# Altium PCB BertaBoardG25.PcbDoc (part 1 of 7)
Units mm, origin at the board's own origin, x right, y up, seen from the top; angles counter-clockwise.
Board outline 160 x 160 mm, 4 copper layers (Top, GND Plane, Power Plane, Bottom), stack 1.344 mm thick; 17 components, 112 nets, 2311 pads, 138 vias.
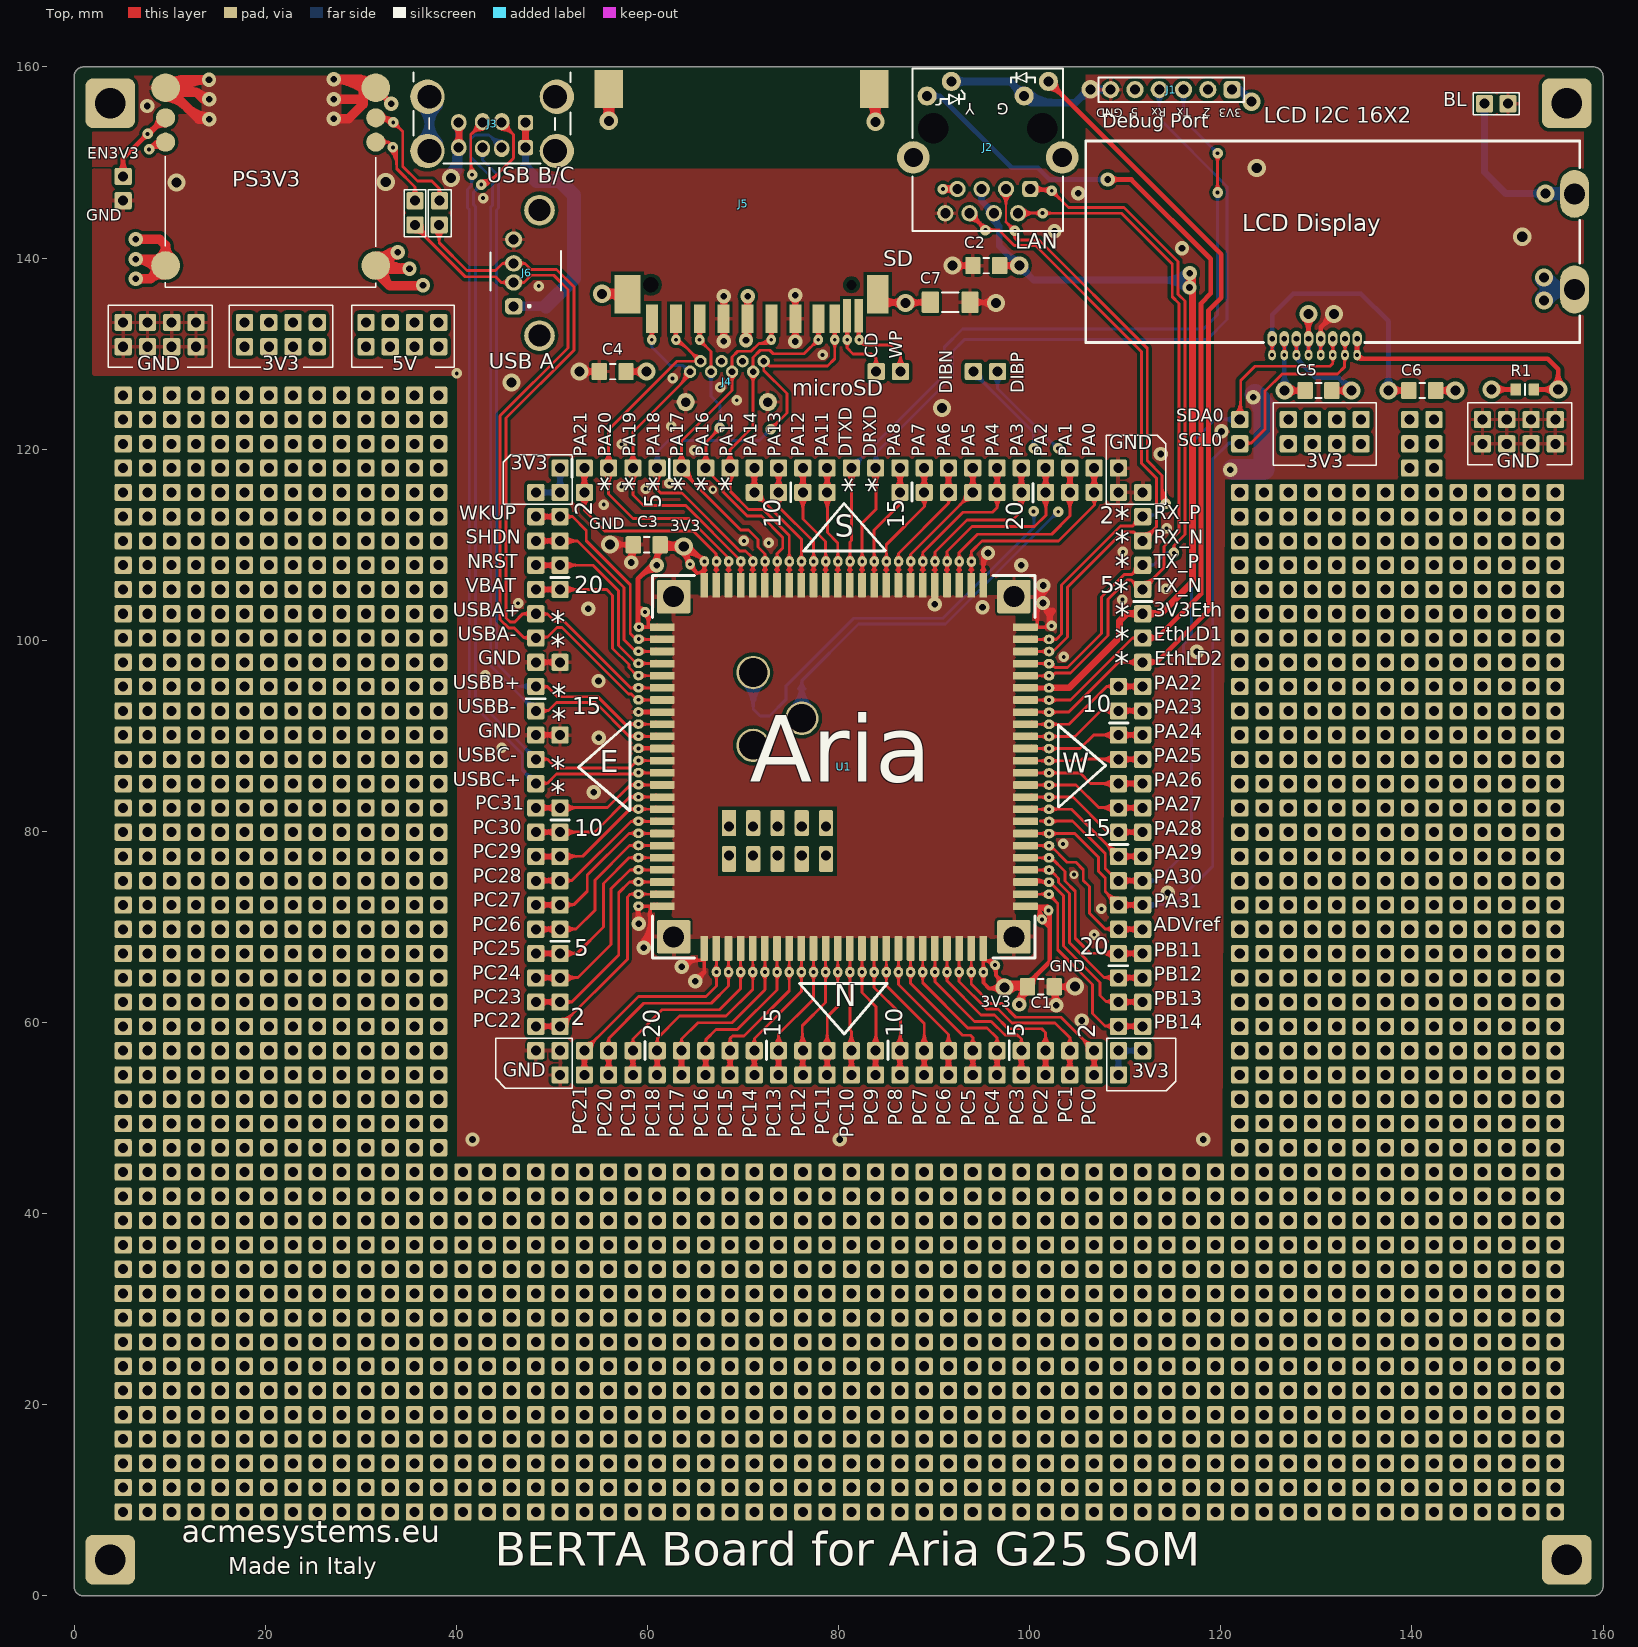
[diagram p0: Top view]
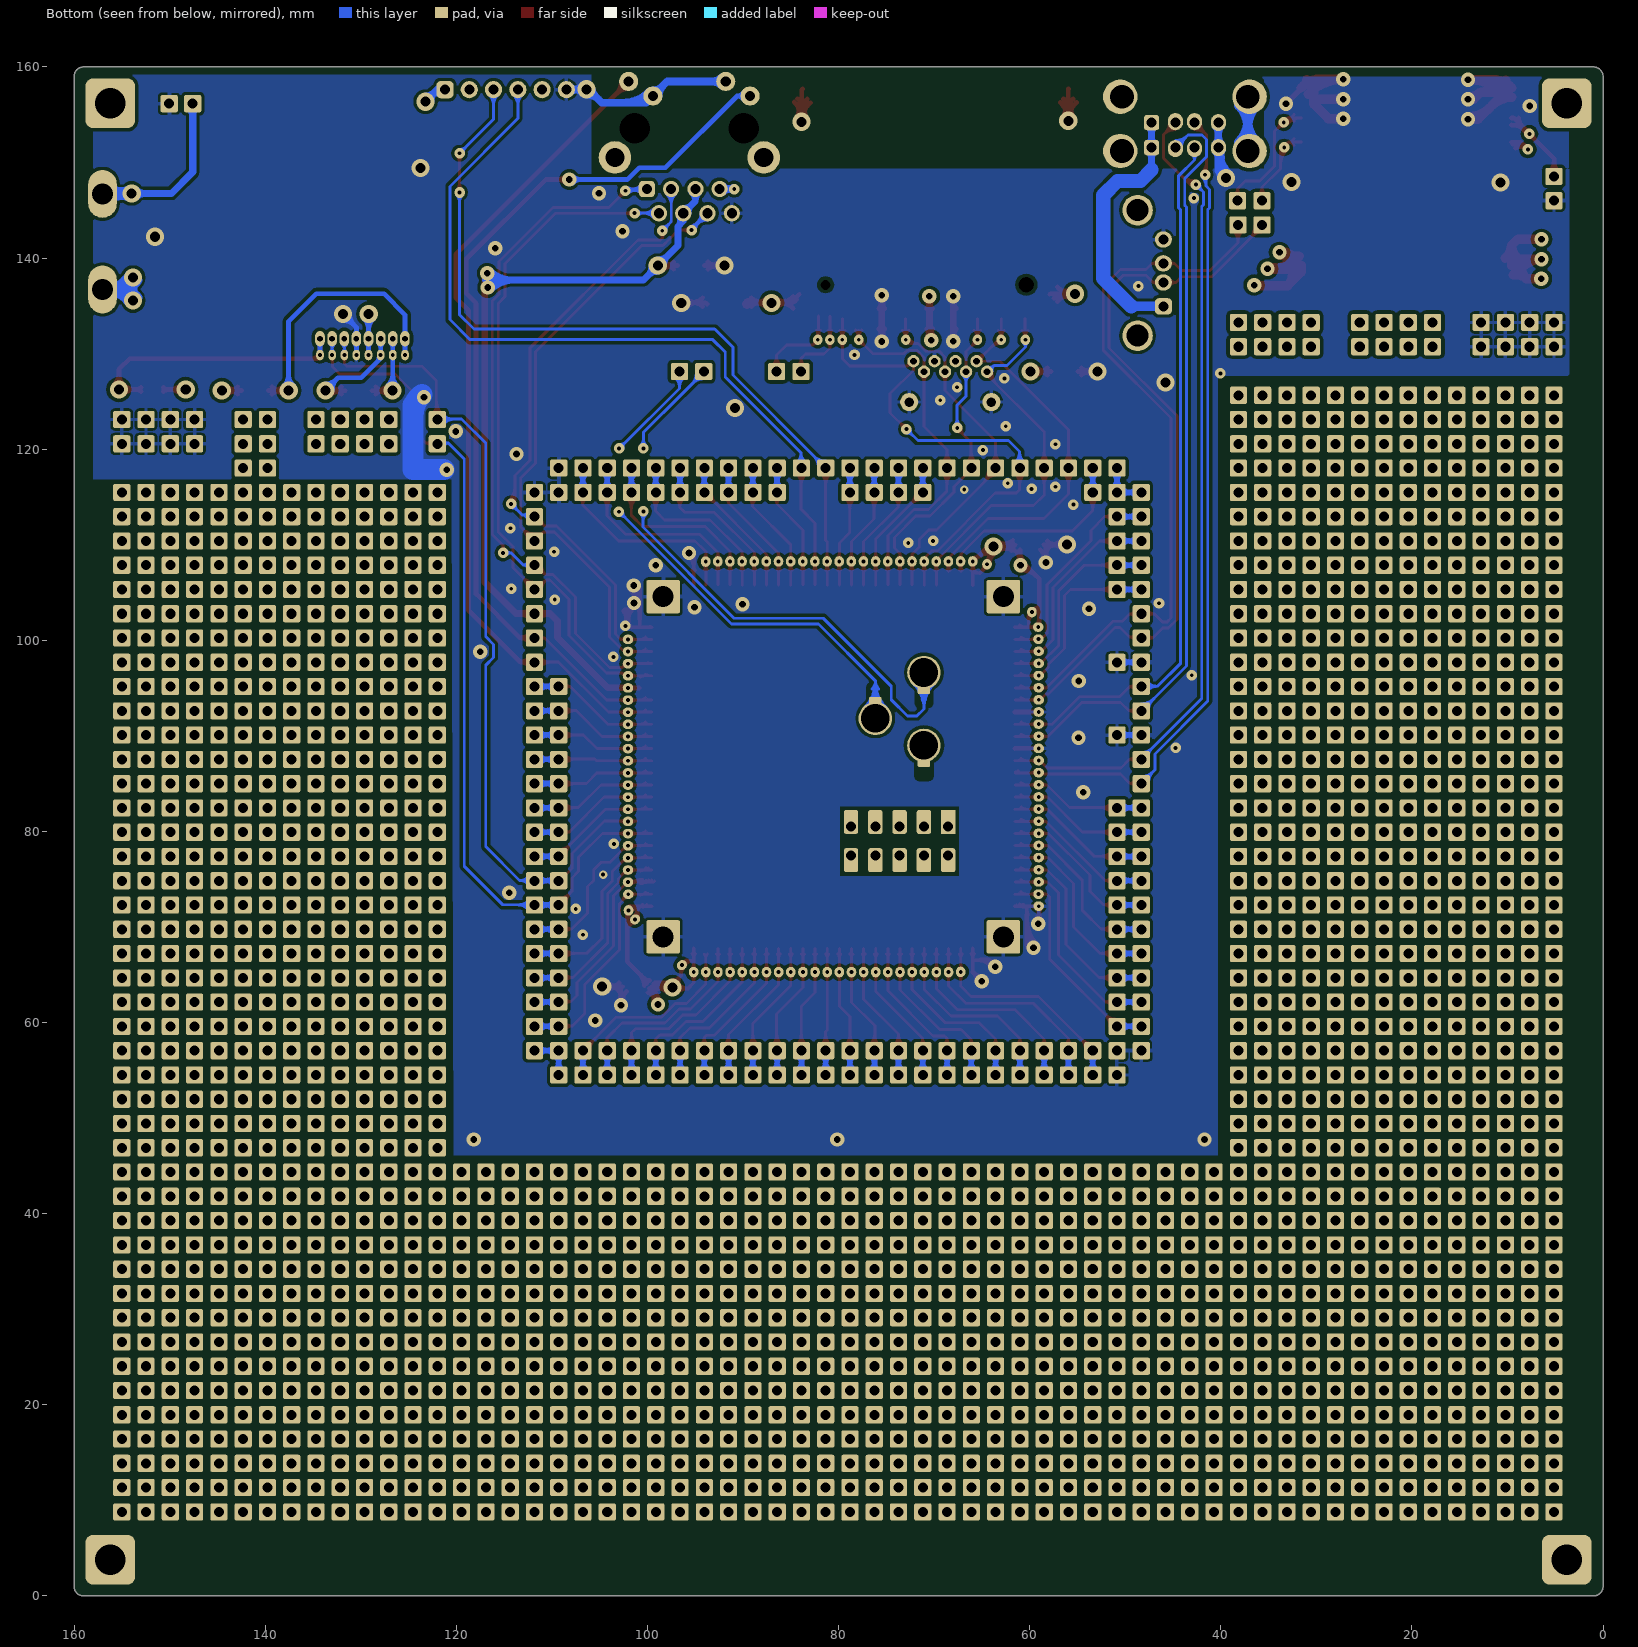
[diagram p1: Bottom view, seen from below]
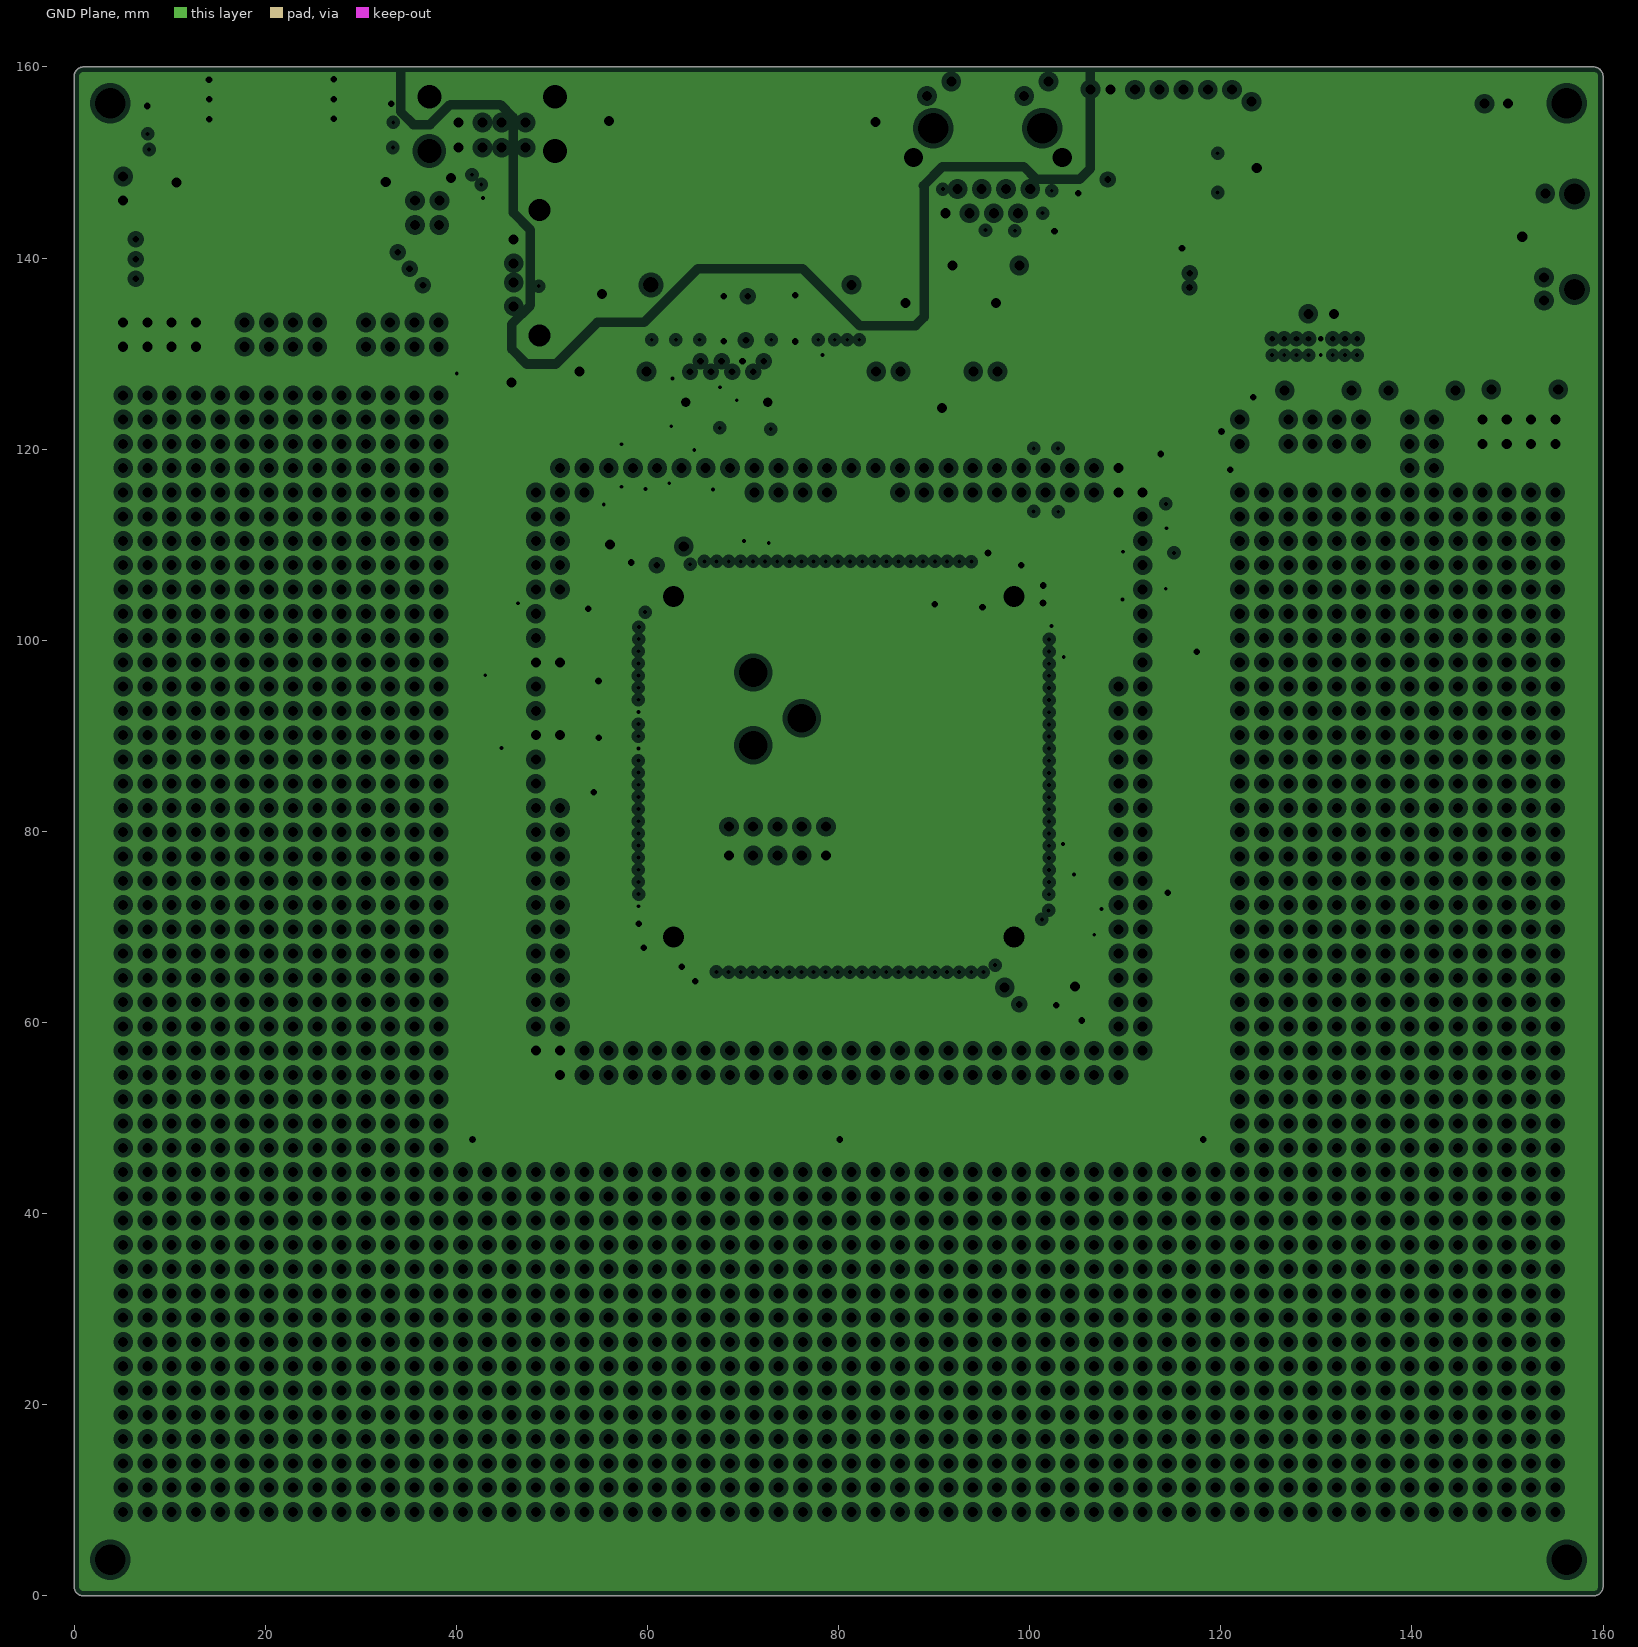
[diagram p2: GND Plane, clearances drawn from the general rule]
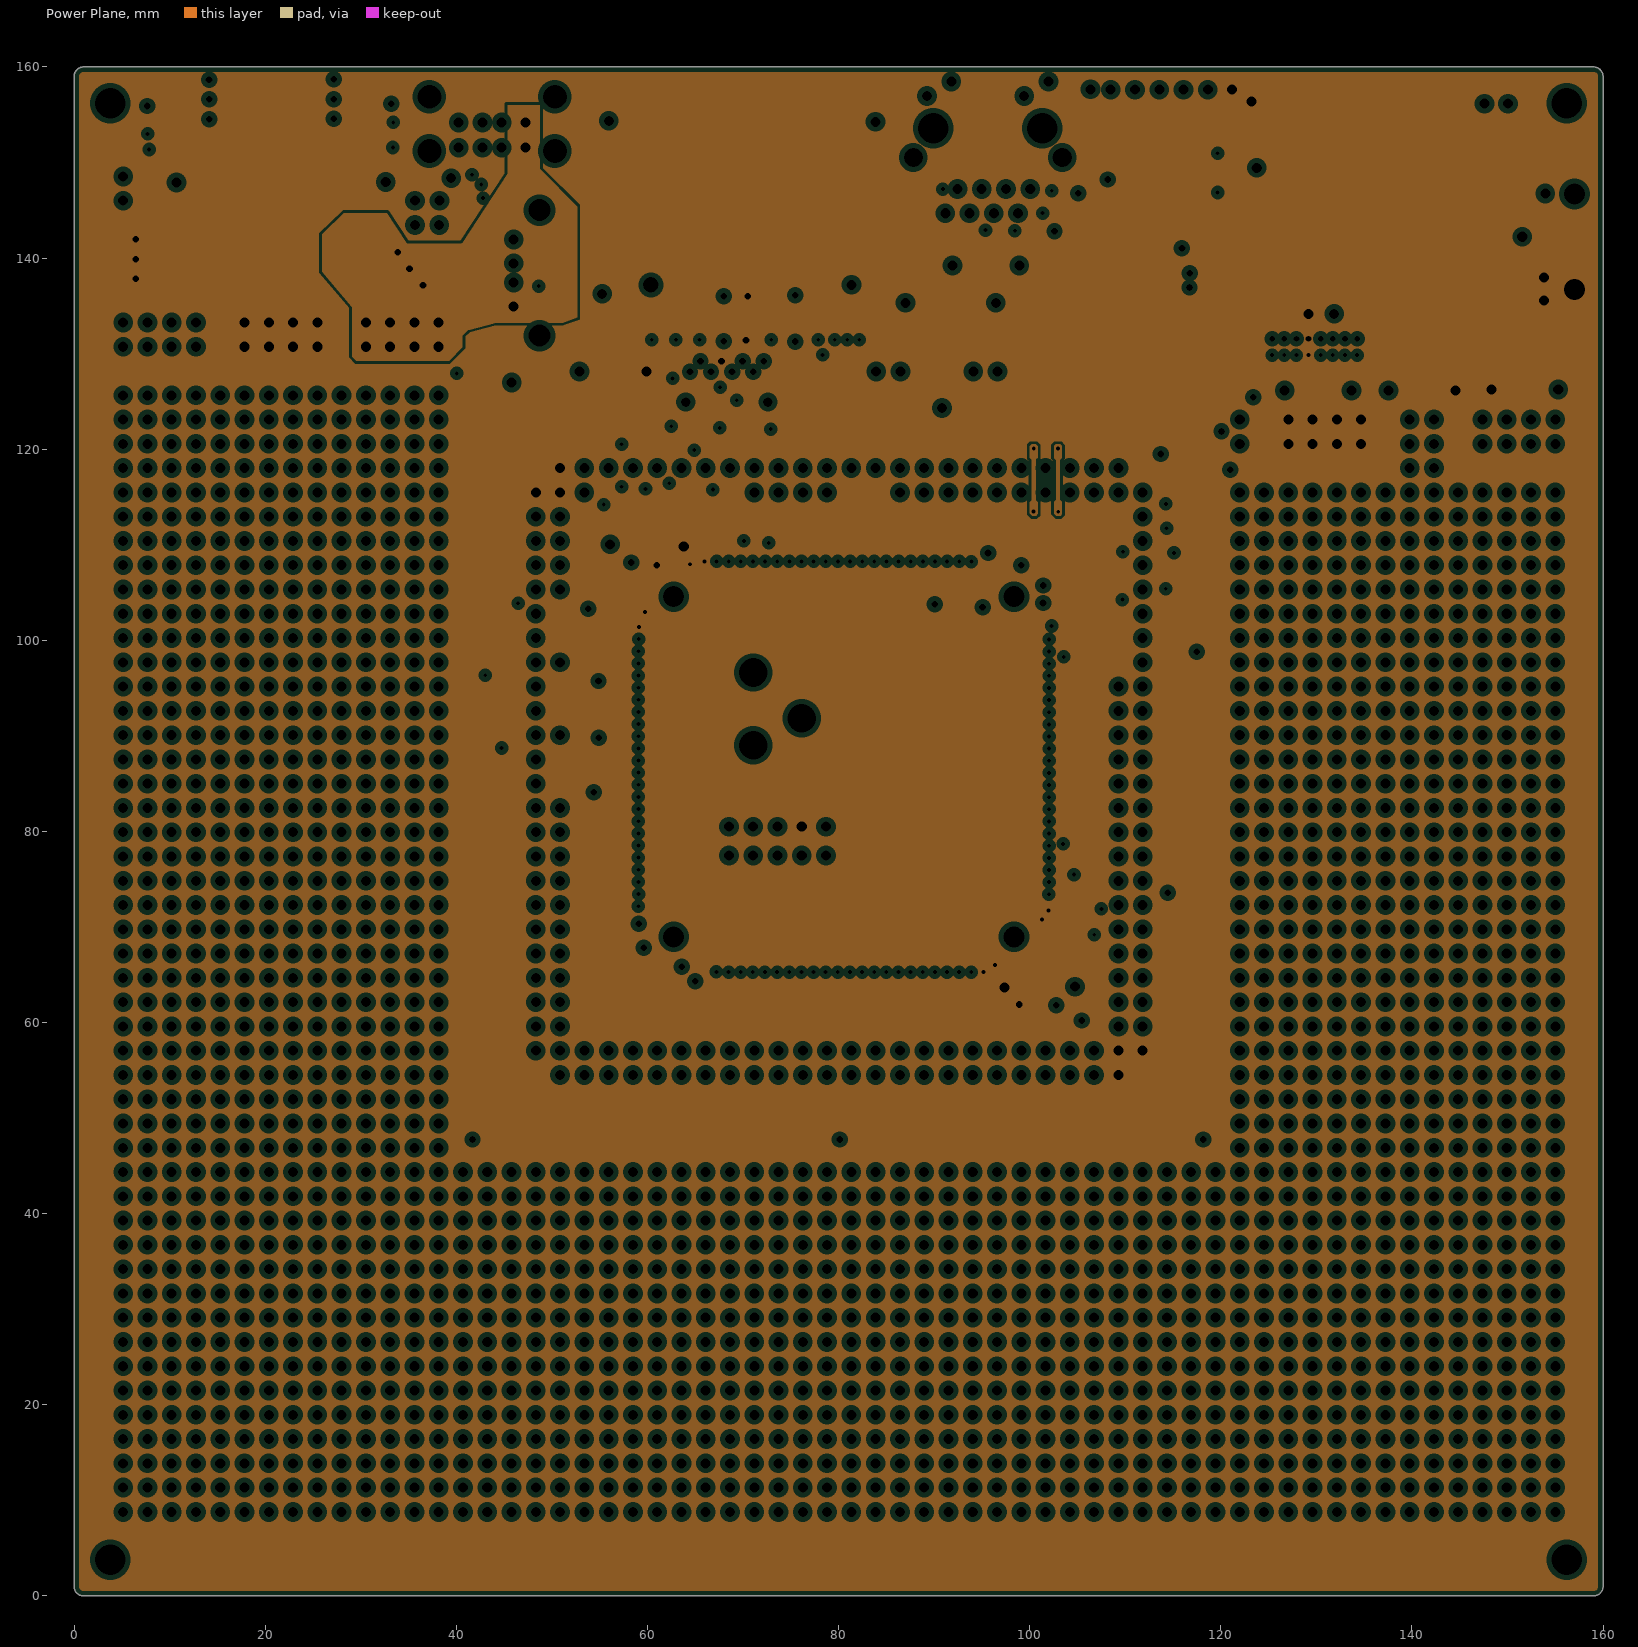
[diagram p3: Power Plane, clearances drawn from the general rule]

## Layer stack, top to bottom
Top: signal copper 0.017
Dielectric: core 0.6, pre preg 1080, Dk 4.8
GND Plane: plane copper 0.035, net (Multiple Nets)
Dielectric: prepreg 0.32, FR-4, Dk 4.8
Power Plane: plane copper 0.035, net (Multiple Nets)
Dielectric: core 0.32, FR-4, Dk 4.8
Bottom: signal copper 0.017

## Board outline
1,0 cw(c1.012,1.011) 0,1.023 0,159 0.001,159 cw(c1.012,158.988) 1.024,160 1,160 159,160 cw(c158.988,158.989) 160,158.977 160,1 cw(c158.989,1.012) 158.977,0

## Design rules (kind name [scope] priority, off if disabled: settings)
Clearance Clearance_Polygon [(IsPad or IsTrack or isVia) vs IsRegion] p1: gap=0.35
Clearance [All] p2: gap=0.29
ComponentClearance [All] p1: gap=0.254 collisioncheckmode=3 verticalgap=0.02 showdistances=FALSE
DiffPairsRouting [All] p1: maxlimit=0.254 minlimit=0.254 mostfreqgap=0.254 maxuncoupledlength=12.7
FabricationTestPointUsage TestPointUsage [All] p1: valid=0 allowmultiple=FALSE
FabricationTestpoint Testpoint [All] p1: side=3 testpointundercomponent=TRUE minsize=1.016 maxsize=2.54 preferedsize=1.524 minholesize=0 maxholesize=1.016 preferedholesize=0.813 testpointgrid=0.025 allowsidetop=TRUE allowsidebottom=TRUE usegrid=TRUE gridtolerance=0
HoleSize [All] p1: absolutevalues=TRUE maxlimit=4 minlimit=0.025 maxpercent=80.000 minpercent=20.000
HoleToHoleClearance [All] p1: gap=0.6 allowstackedmicrovias=TRUE
MinimumSolderMaskSliver [All] p1: minsoldermaskwidth=0.14
PasteMaskExpansion [All] p1: expansion=-0.025
PlaneClearance [All] p1: clearance=0.508
PlaneConnect [InNet('DIBN') or InNet('DIBP')] p1: planeconnectstyle=Direct reliefexpansion=0.508 reliefentries=4 reliefconductorwidth=0.3 reliefairgap=0.3
PlaneConnect PlaneConnect_1 [All] p2: planeconnectstyle=Relief reliefexpansion=0.508 reliefentries=4 reliefconductorwidth=0.35 reliefairgap=0.3
PolygonConnect Pads [(InPadClass('All Pads'))] p1: connectstyle=Relief reliefconductorwidth=0.4 reliefentries=4 polygonreliefangle="90 Angle" airgapwidth=0.254
PolygonConnect "Not Pads" [(NOT(InPadClass('All Pads')))] p2: connectstyle=Direct reliefconductorwidth=0.254 reliefentries=4 polygonreliefangle="90 Angle" airgapwidth=0.254
RoomDefinition BertaBoardG25 [InComponentClass('BertaBoardG25')] p1: confinementstyle=ConfineIn formatcopy=TRUE lockcomponents=FALSE outline -18.32,-12.99 353.11,-12.99 353.11,189.7 -18.32,189.7
RoutingVias [All] p1: holewidth=0.7 width=1.3 viastyle="Through Hole" minholewidth=0.4 minwidth=0.9 maxholewidth=1.1 maxwidth=1.9
ShortCircuit [All] p1: allowed=TRUE
SilkToSilkClearance [All] p1: silktosilkclearance=0.17
SilkToSolderMaskClearance SilkscreenOverComponentPads [IsPad] p1: minsilkscreentomaskgap=0.154 clearancetoexposedcopper=TRUE
SolderMaskExpansion [All] p1: expansion=0.075
Width [All] p1: maxlimit=3 minlimit=0.25 preferedwidth=0.5
15 further rules are at their usual default settings.

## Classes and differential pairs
differential pair USBC: +USBC_P -USBC_N
differential pair USBB: +USBB_P -USBB_N
differential pair USBA: +USBA_P -USBA_N
differential pair TX: +TX_P -TX_N
differential pair RX: +RX_P -RX_N

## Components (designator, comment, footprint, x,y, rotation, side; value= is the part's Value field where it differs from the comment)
C1 "47uF" "CC 1206 (3216 metric)" 101.174,63.749 r0 top
C2 "47uF" "CC 1206 (3216 metric)" 95.458,139.211 r180 top
C3 "47uF" "CC 1206 (3216 metric)" 59.928,109.99 r180 top (schematic designator C1)
C4 "47uF" "CC 1206 (3216 metric)" 56.359,128.122 r180 top
C5 "1uF" "CC 1206 (3216 metric)" 130.222,126.143 r0 top
C6 "1uF" "CC 1206 (3216 metric)" 141.079,126.143 r0 top
C7 "CC 1nF 1808 3kV" "CC 1808 (4520 metric)" 91.679,135.383 r180 top
J1 "JJ HDR1X6 6mm M" "HDR1X6 3D" 121.18,157.62 r180 top (schematic designator J3)
J2 "JJ RJLD260TC1 ETH" RJLD-260TC1 95.614,150.528 r180 top
J3 "JJ USB A Double 90" USB2.0-double-FCI72309 47.252,151.553 r180 top
J4 "JJ Vert_uSD" "JJ Vert_uSD" 64.458,128.103 r90 top
J5 "JJ SDCARD 9P" "JJ SDCARD 9P" 84.252,159.103 r180 top
J6 "JJ USB A" USB2.0-Vert 46.009,141.947 r90 top
"LCD Display" "LCD Daisy 24" "LCD Daisy24" 131.718,141.711 r0 top (schematic designator "Display LCD")
PS3V3 "PS3V3" "AB PS3V3" 9.579,137.019 r0 top
R1 "RR 1k 0402 5%" "RR 0805 (2012 metric)" 151.819,126.243 r0 top
U1 "ARIA" "AB ARIA 2" 60.551,66.77 r180 top

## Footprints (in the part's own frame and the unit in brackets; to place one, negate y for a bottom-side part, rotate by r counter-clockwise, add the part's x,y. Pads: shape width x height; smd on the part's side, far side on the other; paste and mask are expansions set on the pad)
"AB ARIA 2" [mm]
  rect 1.5x2.5 hole 1.05 copper offset 0,-0.5 paste-0.1: 1(-7.98,-13.725)
  rect 1.5x2.2 smd paste+0.1: 1(-7.98,-13.83)
  rrect30% 1.5x2.5 hole 1.05 copper offset 0,0.5 paste-0.1: 2(-7.98,-10.725) 4(-10.52,-10.725) 6(-13.06,-10.725) 8(-15.6,-10.725) 10(-18.14,-10.725)
  rrect30% 1.5x2.2 smd paste+0.1: 2(-7.98,-10.62) 3(-10.52,-13.83) 4(-10.52,-10.62) 5(-13.06,-13.83) 6(-13.06,-10.62) 7(-15.6,-13.83) 8(-15.6,-10.62) 9(-18.14,-13.83) 10(-18.14,-10.62)
  rrect30% 1.5x2.5 hole 1.05 copper offset 0,-0.5 paste-0.1: 3(-10.52,-13.725) 5(-13.06,-13.725) 7(-15.6,-13.725) 9(-18.14,-13.725)
  round 3.5 hole 3 paste-1 mask+0.1: 11(-10.52,-22.24) 12(-15.6,-25.07) 13(-10.52,-29.86)
  rrect20% 1.3x2.25 smd far side: 11(-10.52,-21.115) 12(-15.6,-26.195) 13(-10.52,-28.735)
  rrect20% 2.6x0.8 smd paste+0.05 mask+0.05: E1(-1,-5.395) E2(-1,-6.665) E3(-1,-7.935) E4(-1,-9.205) E5(-1,-10.475) E6(-1,-11.745) E7(-1,-13.015) E8(-1,-14.285) E9(-1,-15.555) E10(-1,-16.825) E11(-1,-18.095) E12(-1,-19.365) E13(-1,-20.635) E14(-1,-21.905) E15(-1,-23.175) E16(-1,-24.445) E17(-1,-25.715) E18(-1,-26.985) E19(-1,-28.255) E20(-1,-29.525) E21(-1,-30.795) E22(-1,-32.065) E23(-1,-33.335) E24(-1,-34.605) W1(-39,-34.605) W2(-39,-33.335) W3(-39,-32.065) W4(-39,-30.795) W5(-39,-29.525) W6(-39,-28.255) W7(-39,-26.985) W8(-39,-25.715) W9(-39,-24.445) W10(-39,-23.175) W11(-39,-21.905) W12(-39,-20.635) W13(-39,-19.365) W14(-39,-18.095) W15(-39,-16.825) W16(-39,-15.555) W17(-39,-14.285) W18(-39,-13.015) W19(-39,-11.745) W20(-39,-10.475) W21(-39,-9.205) W22(-39,-7.935) W23(-39,-6.665) W24(-39,-5.395)
  rrect10% 3.5x3.5 hole 2.2 mask+0.2: H1(-37.8,-2.2) H2(-2.2,-2.2) H3(-2.2,-37.8) H4(-37.8,-37.8)
  rrect20% 0.8x2.6 smd paste+0.05 mask+0.05: N1(-34.605,-1) N2(-33.335,-1) N3(-32.065,-1) N4(-30.795,-1) N5(-29.525,-1) N6(-28.255,-1) N7(-26.985,-1) N8(-25.715,-1) N9(-24.445,-1) N10(-23.175,-1) N11(-21.905,-1) N12(-20.635,-1) N13(-19.365,-1) N14(-18.095,-1) N15(-16.825,-1) N16(-15.555,-1) N17(-14.285,-1) N18(-13.015,-1) N19(-11.745,-1) N20(-10.475,-1) N21(-9.205,-1) N22(-7.935,-1) N23(-6.665,-1) N24(-5.395,-1) S1(-5.395,-39) S2(-6.665,-39) S3(-7.935,-39) S4(-9.205,-39) S5(-10.475,-39) S6(-11.745,-39) S7(-13.015,-39) S8(-14.285,-39) S9(-15.555,-39) S10(-16.825,-39) S11(-18.095,-39) S12(-19.365,-39) S13(-20.635,-39) S14(-21.905,-39) S15(-23.175,-39) S16(-24.445,-39) S17(-25.715,-39) S18(-26.985,-39) S19(-28.255,-39) S20(-29.525,-39) S21(-30.795,-39) S22(-32.065,-39) S23(-33.335,-39) S24(-34.605,-39)
  silkscreen extent -40,-40 0,0, body extent -40.05,-40.05 0.05,0.05, height 2.75
"AB PS3V3" [mm]
  round 3 smd: 1(0,20.8) 4(0,2.2) 5(22,2.2) 8(22,20.8)
  round 2 smd: 2(0,17.65) 3(0,15.11) 6(22,15.113) 7(22,17.653)
  body extent 0,0 22,24.83, height 5.74
"CC 1206 (3216 metric)" [mm] "Generic chip capacitor"
  rrect15% 1.6x1.8 smd paste-0.05: 1(-1.4,0) 2(1.4,0)
  silkscreen extent -0.3,-0.8 0.3,0.8, body extent -1.6,-0.8 1.6,0.8, height 1.6
"CC 1808 (4520 metric)" [mm] "Generic chip capacitor"
  rrect15% 1.8x2.25 smd: 1(-2.075,0) 2(2.075,0)
  silkscreen extent -0.87,-1.02 0.87,1.02, body extent -2.25,-1 2.25,1, height 2.03
"HDR1X6 3D" [mm] "Connector; Header; 6 Position"
  rrect50% 1.8x1.8 hole 1.05: 1(0,0)
  round 1.8 hole 1.05: 2(2.54,0) 3(5.08,0) 4(7.62,0) 5(10.16,0) 6(12.7,0)
  silkscreen extent -1.27,-1.27 13.97,1.27, body extent -1.08,-1.16 13.76,1.18, height 8.23
"JJ SDCARD 9P" [mm]
  round 0 hole 1.05 mask+0.65: 1(2.9,21.9)
  rect 1.25x3 smd mask+0.05: 1(21.275,25.45) 2(18.775,25.45) 3(16.275,25.45) 4(13.775,25.45) 5(11.275,25.45) 6(8.775,25.45) 7(6.35,25.45) 9(23.775,25.45)
  round 0 hole 1.6 mask+0.9: 2(23.9,21.9)
  rect 1.1x3 smd mask+0.05: 8(4.65,25.45)
  rect 3x4 smd mask+0.05: 10(0.5,1.4) 11(28.3,1.4)
  rect 2.7x4 smd mask+0.05: 12(26.35,22.9)
  rect 2.3x4 smd mask+0.05: 13(0.15,22.9)
  rect 0.85x3.5 smd mask+0.05: CD(3.35,25.15)
  rect 0.9x3.5 smd mask+0.05: WP(2.15,25.15)
  body extent 0.37,-1.08 28.35,25.17, height 3.32
"JJ Vert_uSD" [mm]
  round 1.3 hole 0.7 mask+0.05: 1(0,0) 2(1.1,-1.1) 3(0,-2.2) 4(1.1,-3.3) 5(0,-4.4) 6(1.1,-5.5) 7(0,-6.6) 8(1.1,-7.7)
  round 1.9 hole 1 mask+0.05: 9(-3.17,-8.15) 10(-3.17,0.45)
  body extent -3.47,-10.35 1.35,2.65, height 14.18
"LCD Daisy24" [mm] "Dispaly LCD"
  oval 1x1.6 hole 0.6 mask+0.05: 1(-6.345,-10.15) 2(-5.074,-10.149) 3(-3.805,-10.15) 4(-2.535,-10.15) 5(-1.264,-10.149) 6(0,-10.15) 7(1.275,-10.15) 8(2.545,-10.15)
  oval 3x5 hole 2.2 mask+0.05: 9(25.3,-5) 10(25.3,5)
  body extent -25.6,-10.35 25.6,10.35, height 6.3
RJLD-260TC1 [mm] "RJ45 Ethernet connector by TAIMAG"
  rrect50% 1.7x1.7 hole 1.05: 1(-4.445,3.3)
  round 1.7 hole 1.05: 2(-3.175,5.84) 3(-1.905,3.3) 4(-0.635,5.84) 5(0.635,3.3) 6(1.905,5.84) 7(3.175,3.3) 8(4.445,5.84)
  round 2 hole 1.05: 9(-6.35,-7.95) 10(-3.81,-6.43) 11(3.81,-7.95) 12(6.35,-6.43)
  round 3.4 hole 2: 13(-7.79,0) 14(7.79,0)
  round 2.95 hole 3.2 unplated mask+0.2: MH3(-5.715,-3.05) MH4(5.715,-3.05)
  silkscreen extent -7.89,-9.3 7.88,7.71, body extent -8.88,-14.28 9.02,6.72, height 14.57
"RR 0805 (2012 metric)" [mm] "Chip Resistor - Surface Mount 0805 (2012 metric)"
  rrect15% 1.1x1.3 smd: 1(0.95,0) 2(-0.95,0)
  silkscreen extent 0,-0.6 0,0.6, body extent -1,-0.63 1,0.63, height 0.45
USB2.0-double-FCI72309 [mm] "Connector; USB2.0, Type A, Thru-Hole; 4+4 Position; Right Angle: Tyco 5787617; 4U 05243"
  rrect40% 1.6x1.6 hole 1.05: 1(0,0) 5(0,-2.62)
  oval 1.6x1.8 hole 1.05 copper offset 0,0.1: 2(2.5,0) 3(4.5,0)
  oval 1.6x1.8 hole 1.05: 4(7,0) 8(7,-2.62)
  oval 1.6x1.8 hole 1.05 copper offset 0,-0.1: 6(2.5,-2.62) 7(4.5,-2.62)
  round 3.6 hole 2.5 copper offset -0.2,0: 9(-3.07,0.35) 10(-3.07,-5.33)
  round 3.6 hole 2.5 copper offset 0.2,0: 11(10.07,-5.33) 12(10.07,0.35)
  silkscreen extent -4.72,-7.84 11.73,1.67, body extent -4.62,-15.59 11.62,1.59, height 15.78
USB2.0-Vert [mm] "Connector; USB2.0 Type A, Thru-Hole; 4 Position; Vertical"
  rrect50% 1.7x1.8 hole 1.05 mask+0.05: 1(-7,0)
  oval 1.7x1.8 hole 1.05 mask+0.05: 2(-4.5,0) 3(-2.5,0) 4(0,0)
  round 3.2 hole 2.3: 5(-10.07,-2.7) 6(3.07,-2.7)
  silkscreen extent -7.11,-4.95 -1.21,2.43, body extent -11.4,-4.83 4.4,2.3, height 15.1

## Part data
C1 C2 C3 C4 C5 C6: library part "CC Ceramic", "Capacitor, Multi Layer Ceramic"
C7: library part "CAP NP"
J1: library part "Header 6", "Header, 6-Pin"
J2: "ETH connector RJLD-260TC1 TAIMAG"
J3: "USB2.0 Double type A connector"
J6: "USB 2.0 type A"
"LCD Display": "EZL display"
PS3V3: library part "AB PS3V3"
R1: library part "RR Resistor", "Resistor"

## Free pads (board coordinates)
  rrect20% 1.8x1.8 hole 1.05: 0(5.142,8.8) 0(5.142,11.34) 0(5.142,13.88) 0(5.142,16.42) 0(5.142,18.96) 0(5.142,21.5) 0(5.142,24.04) 0(5.142,26.58) 0(5.142,29.12) 0(5.142,31.66) 0(5.142,34.2) 0(5.142,36.74) 0(5.142,39.28) 0(5.142,41.82) 0(5.142,44.36) 0(5.142,46.9) 0(5.142,49.44) 0(5.142,51.98) 0(5.142,54.52) 0(5.142,57.06) 0(5.142,59.6) 0(5.142,62.14) 0(5.142,64.68) 0(5.142,67.22) 0(5.142,69.76) 0(5.142,72.3) 0(5.142,74.84) 0(5.142,77.38) 0(5.142,79.92) 0(5.142,82.46) 0(5.142,85) 0(5.142,87.54) 0(5.142,90.08) 0(5.142,92.62) 0(5.142,95.16) 0(5.142,97.7) 0(5.142,100.24) 0(5.142,102.78) 0(5.142,105.32) 0(5.142,107.86) 0(5.142,110.4) 0(5.142,112.94) 0(5.142,115.48) 0(5.142,118.02) 0(5.142,120.56) 0(5.142,123.1) 0(5.142,125.64) 0(5.142,130.72) 0(5.142,133.26) 0(5.142,146) 0(5.142,148.54) 0(7.682,8.8) 0(7.682,11.34) 0(7.682,13.88) 0(7.682,16.42) 0(7.682,18.96) 0(7.682,21.5) 0(7.682,24.04) 0(7.682,26.58) 0(7.682,29.12) 0(7.682,31.66) 0(7.682,34.2) 0(7.682,36.74) 0(7.682,39.28) 0(7.682,41.82) 0(7.682,44.36) 0(7.682,46.9) 0(7.682,49.44) 0(7.682,51.98) 0(7.682,54.52) 0(7.682,57.06) 0(7.682,59.6) 0(7.682,62.14) 0(7.682,64.68) 0(7.682,67.22) 0(7.682,69.76) 0(7.682,72.3) 0(7.682,74.84) 0(7.682,77.38) 0(7.682,79.92) 0(7.682,82.46) 0(7.682,85) 0(7.682,87.54) 0(7.682,90.08) 0(7.682,92.62) 0(7.682,95.16) 0(7.682,97.7) 0(7.682,100.24) 0(7.682,102.78) 0(7.682,105.32) 0(7.682,107.86) 0(7.682,110.4) 0(7.682,112.94) 0(7.682,115.48) 0(7.682,118.02) 0(7.682,120.56) 0(7.682,123.1) 0(7.682,125.64) 0(7.682,130.72) 0(7.682,133.26) 0(10.222,8.8) 0(10.222,11.34) 0(10.222,13.88) 0(10.222,16.42) 0(10.222,18.96) 0(10.222,21.5) 0(10.222,24.04) 0(10.222,26.58) 0(10.222,29.12) 0(10.222,31.66) 0(10.222,34.2) 0(10.222,36.74) 0(10.222,39.28) 0(10.222,41.82) 0(10.222,44.36) 0(10.222,46.9) 0(10.222,49.44) 0(10.222,51.98) 0(10.222,54.52) 0(10.222,57.06) 0(10.222,59.6) 0(10.222,62.14) 0(10.222,64.68) 0(10.222,67.22) 0(10.222,69.76) 0(10.222,72.3) 0(10.222,74.84) 0(10.222,77.38) 0(10.222,79.92) 0(10.222,82.46) 0(10.222,85) 0(10.222,87.54) 0(10.222,90.08) 0(10.222,92.62) 0(10.222,95.16) 0(10.222,97.7) 0(10.222,100.24) 0(10.222,102.78) 0(10.222,105.32) 0(10.222,107.86) 0(10.222,110.4) 0(10.222,112.94) 0(10.222,115.48) 0(10.222,118.02) 0(10.222,120.56) 0(10.222,123.1) 0(10.222,125.64) 0(10.222,130.72) 0(10.222,133.26) 0(12.762,8.8) 0(12.762,11.34) 0(12.762,13.88) 0(12.762,16.42) 0(12.762,18.96) 0(12.762,21.5) 0(12.762,24.04) 0(12.762,26.58) 0(12.762,29.12) 0(12.762,31.66) 0(12.762,34.2) 0(12.762,36.74) 0(12.762,39.28) 0(12.762,41.82) 0(12.762,44.36) 0(12.762,46.9) 0(12.762,49.44) 0(12.762,51.98) 0(12.762,54.52) 0(12.762,57.06) 0(12.762,59.6) 0(12.762,62.14) 0(12.762,64.68) 0(12.762,67.22) 0(12.762,69.76) 0(12.762,72.3) 0(12.762,74.84) 0(12.762,77.38) 0(12.762,79.92) 0(12.762,82.46) 0(12.762,85) 0(12.762,87.54) 0(12.762,90.08) 0(12.762,92.62) 0(12.762,95.16) 0(12.762,97.7) 0(12.762,100.24) 0(12.762,102.78) 0(12.762,105.32) 0(12.762,107.86) 0(12.762,110.4) 0(12.762,112.94) 0(12.762,115.48) 0(12.762,118.02) 0(12.762,120.56) 0(12.762,123.1) 0(12.762,125.64) 0(12.762,130.72) 0(12.762,133.26) 0(15.302,8.8) 0(15.302,11.34) 0(15.302,13.88) 0(15.302,16.42) 0(15.302,18.96) 0(15.302,21.5) 0(15.302,24.04) 0(15.302,26.58) 0(15.302,29.12) 0(15.302,31.66) 0(15.302,34.2) 0(15.302,36.74) 0(15.302,39.28) 0(15.302,41.82) 0(15.302,44.36) 0(15.302,46.9) 0(15.302,49.44) 0(15.302,51.98) 0(15.302,54.52) 0(15.302,57.06) 0(15.302,59.6) 0(15.302,62.14) 0(15.302,64.68) 0(15.302,67.22) 0(15.302,69.76) 0(15.302,72.3) 0(15.302,74.84) 0(15.302,77.38) 0(15.302,79.92) 0(15.302,82.46) 0(15.302,85) 0(15.302,87.54) 0(15.302,90.08) 0(15.302,92.62) 0(15.302,95.16) 0(15.302,97.7) 0(15.302,100.24) 0(15.302,102.78) 0(15.302,105.32) 0(15.302,107.86) 0(15.302,110.4) 0(15.302,112.94) 0(15.302,115.48) 0(15.302,118.02) 0(15.302,120.56) 0(15.302,123.1) 0(15.302,125.64) 0(17.842,8.8) 0(17.842,11.34) 0(17.842,13.88) 0(17.842,16.42) 0(17.842,18.96) 0(17.842,21.5) 0(17.842,24.04) 0(17.842,26.58) 0(17.842,29.12) 0(17.842,31.66) 0(17.842,34.2) 0(17.842,36.74) 0(17.842,39.28) 0(17.842,41.82) 0(17.842,44.36) 0(17.842,46.9) 0(17.842,49.44) 0(17.842,51.98) 0(17.842,54.52) 0(17.842,57.06) 0(17.842,59.6) 0(17.842,62.14) 0(17.842,64.68) 0(17.842,67.22) 0(17.842,69.76) 0(17.842,72.3) 0(17.842,74.84) 0(17.842,77.38) 0(17.842,79.92) 0(17.842,82.46) 0(17.842,85) 0(17.842,87.54) 0(17.842,90.08) 0(17.842,92.62) 0(17.842,95.16) 0(17.842,97.7) 0(17.842,100.24) 0(17.842,102.78) 0(17.842,105.32) 0(17.842,107.86) 0(17.842,110.4) 0(17.842,112.94) 0(17.842,115.48) 0(17.842,118.02) 0(17.842,120.56) 0(17.842,123.1) 0(17.842,125.64) 0(17.842,130.72) 0(17.842,133.26) 0(20.382,8.8) 0(20.382,11.34) 0(20.382,13.88) 0(20.382,16.42) 0(20.382,18.96) 0(20.382,21.5) 0(20.382,24.04) 0(20.382,26.58) 0(20.382,29.12) 0(20.382,31.66) 0(20.382,34.2) 0(20.382,36.74) 0(20.382,39.28) 0(20.382,41.82) 0(20.382,44.36) 0(20.382,46.9) 0(20.382,49.44) 0(20.382,51.98) 0(20.382,54.52) 0(20.382,57.06) 0(20.382,59.6) 0(20.382,62.14) 0(20.382,64.68) 0(20.382,67.22) 0(20.382,69.76) 0(20.382,72.3) 0(20.382,74.84) 0(20.382,77.38) 0(20.382,79.92) 0(20.382,82.46) 0(20.382,85) 0(20.382,87.54) 0(20.382,90.08) 0(20.382,92.62) 0(20.382,95.16) 0(20.382,97.7) 0(20.382,100.24) 0(20.382,102.78) 0(20.382,105.32) 0(20.382,107.86) 0(20.382,110.4) 0(20.382,112.94) 0(20.382,115.48) 0(20.382,118.02) 0(20.382,120.56) 0(20.382,123.1) 0(20.382,125.64) 0(20.382,130.72) 0(20.382,133.26) 0(22.922,8.8) 0(22.922,11.34) 0(22.922,13.88) 0(22.922,16.42) 0(22.922,18.96) 0(22.922,21.5) 0(22.922,24.04) 0(22.922,26.58) 0(22.922,29.12) 0(22.922,31.66) 0(22.922,34.2) 0(22.922,36.74) 0(22.922,39.28) 0(22.922,41.82) 0(22.922,44.36) 0(22.922,46.9) 0(22.922,49.44) 0(22.922,51.98) 0(22.922,54.52) 0(22.922,57.06) 0(22.922,59.6) 0(22.922,62.14) 0(22.922,64.68) 0(22.922,67.22) 0(22.922,69.76) 0(22.922,72.3) 0(22.922,74.84) 0(22.922,77.38) 0(22.922,79.92) 0(22.922,82.46) 0(22.922,85) 0(22.922,87.54) 0(22.922,90.08) 0(22.922,92.62) 0(22.922,95.16) 0(22.922,97.7) 0(22.922,100.24) 0(22.922,102.78) 0(22.922,105.32) 0(22.922,107.86) 0(22.922,110.4) 0(22.922,112.94) 0(22.922,115.48) 0(22.922,118.02) 0(22.922,120.56) 0(22.922,123.1) 0(22.922,125.64) 0(22.922,130.72) 0(22.922,133.26) 0(25.462,8.8) 0(25.462,11.34) 0(25.462,13.88) 0(25.462,16.42) 0(25.462,18.96) 0(25.462,21.5) 0(25.462,24.04) 0(25.462,26.58) 0(25.462,29.12) 0(25.462,31.66) 0(25.462,34.2) 0(25.462,36.74) 0(25.462,39.28) 0(25.462,41.82) 0(25.462,44.36) 0(25.462,46.9) 0(25.462,49.44) 0(25.462,51.98) 0(25.462,54.52) 0(25.462,57.06) 0(25.462,59.6) 0(25.462,62.14) 0(25.462,64.68) 0(25.462,67.22) 0(25.462,69.76) 0(25.462,72.3) 0(25.462,74.84) 0(25.462,77.38) 0(25.462,79.92) 0(25.462,82.46) 0(25.462,85) 0(25.462,87.54) 0(25.462,90.08) 0(25.462,92.62) 0(25.462,95.16) 0(25.462,97.7) 0(25.462,100.24) 0(25.462,102.78) 0(25.462,105.32) 0(25.462,107.86) 0(25.462,110.4) 0(25.462,112.94) 0(25.462,115.48) 0(25.462,118.02) 0(25.462,120.56) 0(25.462,123.1) 0(25.462,125.64) 0(25.462,130.72) 0(25.462,133.26) 0(28.002,8.8) 0(28.002,11.34) 0(28.002,13.88) 0(28.002,16.42) 0(28.002,18.96) 0(28.002,21.5) 0(28.002,24.04) 0(28.002,26.58) 0(28.002,29.12) 0(28.002,31.66) 0(28.002,34.2) 0(28.002,36.74) 0(28.002,39.28) 0(28.002,41.82) 0(28.002,44.36) 0(28.002,46.9) 0(28.002,49.44) 0(28.002,51.98) 0(28.002,54.52) 0(28.002,57.06) 0(28.002,59.6) 0(28.002,62.14) 0(28.002,64.68) 0(28.002,67.22) 0(28.002,69.76) 0(28.002,72.3) 0(28.002,74.84) 0(28.002,77.38) 0(28.002,79.92) 0(28.002,82.46) 0(28.002,85) 0(28.002,87.54) 0(28.002,90.08) 0(28.002,92.62) 0(28.002,95.16) 0(28.002,97.7) 0(28.002,100.24) 0(28.002,102.78) 0(28.002,105.32) 0(28.002,107.86) 0(28.002,110.4) 0(28.002,112.94) 0(28.002,115.48) 0(28.002,118.02) 0(28.002,120.56) 0(28.002,123.1) 0(28.002,125.64) 0(30.542,8.8) 0(30.542,11.34) 0(30.542,13.88) 0(30.542,16.42) 0(30.542,18.96) 0(30.542,21.5) 0(30.542,24.04) 0(30.542,26.58) 0(30.542,29.12) 0(30.542,31.66) 0(30.542,34.2) 0(30.542,36.74) 0(30.542,39.28) 0(30.542,41.82) 0(30.542,44.36) 0(30.542,46.9) 0(30.542,49.44) 0(30.542,51.98) 0(30.542,54.52) 0(30.542,57.06) 0(30.542,59.6) 0(30.542,62.14) 0(30.542,64.68) 0(30.542,67.22) 0(30.542,69.76) 0(30.542,72.3) 0(30.542,74.84) 0(30.542,77.38) 0(30.542,79.92) 0(30.542,82.46) 0(30.542,85) 0(30.542,87.54) 0(30.542,90.08) 0(30.542,92.62) 0(30.542,95.16) 0(30.542,97.7) 0(30.542,100.24) 0(30.542,102.78) 0(30.542,105.32) 0(30.542,107.86) 0(30.542,110.4) 0(30.542,112.94) 0(30.542,115.48) 0(30.542,118.02) 0(30.542,120.56) 0(30.542,123.1) 0(30.542,125.64) 0(30.542,130.72) 0(30.542,133.26) 0(33.082,8.8) 0(33.082,11.34) 0(33.082,13.88) 0(33.082,16.42) 0(33.082,18.96) 0(33.082,21.5) 0(33.082,24.04) 0(33.082,26.58) 0(33.082,29.12) 0(33.082,31.66) 0(33.082,34.2) 0(33.082,36.74) 0(33.082,39.28) 0(33.082,41.82) 0(33.082,44.36) 0(33.082,46.9) 0(33.082,49.44) 0(33.082,51.98) 0(33.082,54.52) 0(33.082,57.06) 0(33.082,59.6) 0(33.082,62.14) 0(33.082,64.68) 0(33.082,67.22) 0(33.082,69.76) 0(33.082,72.3) 0(33.082,74.84) 0(33.082,77.38) 0(33.082,79.92) 0(33.082,82.46) 0(33.082,85) 0(33.082,87.54) 0(33.082,90.08) 0(33.082,92.62) 0(33.082,95.16) 0(33.082,97.7) 0(33.082,100.24) 0(33.082,102.78) 0(33.082,105.32) 0(33.082,107.86) 0(33.082,110.4) 0(33.082,112.94) 0(33.082,115.48) 0(33.082,118.02) 0(33.082,120.56) 0(33.082,123.1) 0(33.082,125.64) 0(33.082,130.72) 0(33.082,133.26) 0(35.622,8.8) 0(35.622,11.34) 0(35.622,13.88) 0(35.622,16.42) 0(35.622,18.96) 0(35.622,21.5) 0(35.622,24.04) 0(35.622,26.58) 0(35.622,29.12) 0(35.622,31.66) 0(35.622,34.2) 0(35.622,36.74) 0(35.622,39.28) 0(35.622,41.82) 0(35.622,44.36) 0(35.622,46.9) 0(35.622,49.44) 0(35.622,51.98) 0(35.622,54.52) 0(35.622,57.06) 0(35.622,59.6) 0(35.622,62.14) 0(35.622,64.68) 0(35.622,67.22) 0(35.622,69.76) 0(35.622,72.3) 0(35.622,74.84) 0(35.622,77.38) 0(35.622,79.92) 0(35.622,82.46) 0(35.622,85) 0(35.622,87.54) 0(35.622,90.08) 0(35.622,92.62) 0(35.622,95.16) 0(35.622,97.7) 0(35.622,100.24) 0(35.622,102.78) 0(35.622,105.32) 0(35.622,107.86) 0(35.622,110.4) 0(35.622,112.94) 0(35.622,115.48) 0(35.622,118.02) 0(35.622,120.56) 0(35.622,123.1) 0(35.622,125.64) 0(35.622,130.72) 0(35.622,133.26) 0(35.691,143.46) 0(35.691,146) 0(38.162,8.8) 0(38.162,11.34) 0(38.162,13.88) 0(38.162,16.42) 0(38.162,18.96) 0(38.162,21.5) 0(38.162,24.04) 0(38.162,26.58) 0(38.162,29.12) 0(38.162,31.66) 0(38.162,34.2) 0(38.162,36.74) 0(38.162,39.28) 0(38.162,41.82) 0(38.162,44.36) 0(38.162,46.9) 0(38.162,49.44) 0(38.162,51.98) 0(38.162,54.52) 0(38.162,57.06) 0(38.162,59.6) 0(38.162,62.14) 0(38.162,64.68) 0(38.162,67.22) 0(38.162,69.76) 0(38.162,72.3) 0(38.162,74.84) 0(38.162,77.38) 0(38.162,79.92) 0(38.162,82.46) 0(38.162,85) 0(38.162,87.54) 0(38.162,90.08) 0(38.162,92.62) 0(38.162,95.16) 0(38.162,97.7) 0(38.162,100.24) 0(38.162,102.78) 0(38.162,105.32) 0(38.162,107.86) 0(38.162,110.4) 0(38.162,112.94) 0(38.162,115.48) 0(38.162,118.02) 0(38.162,120.56) 0(38.162,123.1) 0(38.162,125.64) 0(38.162,130.72) 0(38.162,133.26) 0(38.211,143.46) 0(38.241,146) 0(40.702,8.8) 0(40.702,11.34) 0(40.702,13.88) 0(40.702,16.42) 0(40.702,18.96) 0(40.702,21.5) 0(40.702,24.04) 0(40.702,26.58) 0(40.702,29.12) 0(40.702,31.66) 0(40.702,34.2) 0(40.702,36.74) 0(40.702,39.28) 0(40.702,41.82) 0(40.702,44.36) 0(43.242,8.8) 0(43.242,11.34) 0(43.242,13.88) 0(43.242,16.42) 0(43.242,18.96) 0(43.242,21.5) 0(43.242,24.04) 0(43.242,26.58) 0(43.242,29.12) 0(43.242,31.66) 0(43.242,34.2) 0(43.242,36.74) 0(43.242,39.28) 0(43.242,41.82) 0(43.242,44.36) 0(45.782,8.8) 0(45.782,11.34) 0(45.782,13.88) 0(45.782,16.42) 0(45.782,18.96) 0(45.782,21.5) 0(45.782,24.04) 0(45.782,26.58) 0(45.782,29.12) 0(45.782,31.66) 0(45.782,34.2) 0(45.782,36.74) 0(45.782,39.28) 0(45.782,41.82) 0(45.782,44.36) 0(48.322,8.8) 0(48.322,11.34) 0(48.322,13.88) 0(48.322,16.42) 0(48.322,18.96) 0(48.322,21.5) 0(48.322,24.04) 0(48.322,26.58) 0(48.322,29.12) 0(48.322,31.66) 0(48.322,34.2) 0(48.322,36.74) 0(48.322,39.28) 0(48.322,41.82) 0(48.322,44.36) 0(48.322,57.06) 0(48.322,59.6) 0(48.322,62.14) 0(48.322,64.68) 0(48.322,67.22) 0(48.322,69.76) 0(48.322,72.3) 0(48.322,74.84) 0(48.322,77.38) 0(48.322,79.92) 0(48.322,82.46) 0(48.322,85) 0(48.322,87.54) 0(48.322,90.08) 0(48.322,92.62) 0(48.322,95.16) 0(48.322,97.7) 0(48.322,100.24) 0(48.322,102.78) 0(48.322,105.32) 0(48.322,107.86) 0(48.322,110.4) 0(48.322,112.94) 0(48.322,115.48) 0(50.862,8.8) 0(50.862,11.34) 0(50.862,13.88) 0(50.862,16.42) 0(50.862,18.96) 0(50.862,21.5) 0(50.862,24.04) 0(50.862,26.58) 0(50.862,29.12) 0(50.862,31.66) 0(50.862,34.2) 0(50.862,36.74) 0(50.862,39.28) 0(50.862,41.82) 0(50.862,44.36) 0(50.862,54.52) 0(50.862,57.06) 0(50.862,59.6) 0(50.862,62.14) 0(50.862,64.68) 0(50.862,67.22) 0(50.862,69.76) 0(50.862,72.3) 0(50.862,74.84) 0(50.862,77.38) 0(50.862,79.92) 0(50.862,82.46) 0(50.862,90.08) 0(50.862,97.7) 0(50.862,105.32) 0(50.862,107.86) 0(50.862,110.4) 0(50.862,112.94) 0(50.862,115.48) 0(50.862,118.02) 0(53.402,8.8) 0(53.402,11.34) 0(53.402,13.88) 0(53.402,16.42) 0(53.402,18.96) 0(53.402,21.5) 0(53.402,24.04) 0(53.402,26.58) 0(53.402,29.12) 0(53.402,31.66) 0(53.402,34.2) 0(53.402,36.74) 0(53.402,39.28) 0(53.402,41.82) 0(53.402,44.36) 0(53.402,54.52) 0(53.402,57.06) 0(53.402,115.48) 0(53.402,118.02) 0(55.942,8.8) 0(55.942,11.34) 0(55.942,13.88) 0(55.942,16.42) 0(55.942,18.96) 0(55.942,21.5) 0(55.942,24.04) 0(55.942,26.58) 0(55.942,29.12) 0(55.942,31.66) 0(55.942,34.2) 0(55.942,36.74) 0(55.942,39.28) 0(55.942,41.82) 0(55.942,44.36) 0(55.942,54.52) 0(55.942,57.06) 0(55.942,118.02) 0(58.482,8.8) 0(58.482,11.34) 0(58.482,13.88) 0(58.482,16.42) 0(58.482,18.96) 0(58.482,21.5) 0(58.482,24.04) 0(58.482,26.58) 0(58.482,29.12) 0(58.482,31.66) 0(58.482,34.2) 0(58.482,36.74) 0(58.482,39.28) 0(58.482,41.82) 0(58.482,44.36) 0(58.482,54.52) 0(58.482,57.06) 0(58.482,118.02) 0(61.022,8.8) 0(61.022,11.34) 0(61.022,13.88) 0(61.022,16.42) 0(61.022,18.96) 0(61.022,21.5) 0(61.022,24.04) 0(61.022,26.58) 0(61.022,29.12) 0(61.022,31.66) 0(61.022,34.2) 0(61.022,36.74) 0(61.022,39.28) 0(61.022,41.82) 0(61.022,44.36) 0(61.022,54.52) 0(61.022,57.06) 0(61.022,118.02) 0(63.562,8.8) 0(63.562,11.34) 0(63.562,13.88) 0(63.562,16.42) 0(63.562,18.96) 0(63.562,21.5) 0(63.562,24.04) 0(63.562,26.58) 0(63.562,29.12) 0(63.562,31.66) 0(63.562,34.2) 0(63.562,36.74) 0(63.562,39.28) 0(63.562,41.82) 0(63.562,44.36) 0(63.562,54.52) 0(63.562,57.06) 0(63.562,118.02) 0(66.102,8.8) 0(66.102,11.34) 0(66.102,13.88) 0(66.102,16.42) 0(66.102,18.96) 0(66.102,21.5) 0(66.102,24.04) 0(66.102,26.58) 0(66.102,29.12) 0(66.102,31.66) 0(66.102,34.2) 0(66.102,36.74) 0(66.102,39.28) 0(66.102,41.82) 0(66.102,44.36) 0(66.102,54.52) 0(66.102,57.06) 0(66.102,118.02) 0(68.642,8.8) 0(68.642,11.34) 0(68.642,13.88) 0(68.642,16.42) 0(68.642,18.96) 0(68.642,21.5) 0(68.642,24.04) 0(68.642,26.58) 0(68.642,29.12) 0(68.642,31.66) 0(68.642,34.2) 0(68.642,36.74) 0(68.642,39.28) 0(68.642,41.82) 0(68.642,44.36) 0(68.642,54.52) 0(68.642,57.06) 0(68.642,118.02) 0(71.182,8.8) 0(71.182,11.34) 0(71.182,13.88) 0(71.182,16.42) 0(71.182,18.96) 0(71.182,21.5) 0(71.182,24.04) 0(71.182,26.58) 0(71.182,29.12) 0(71.182,31.66) 0(71.182,34.2) 0(71.182,36.74) 0(71.182,39.28) 0(71.182,41.82) 0(71.182,44.36) 0(71.182,54.52) 0(71.182,57.06) 0(71.182,115.48) 0(71.182,118.02) 0(73.722,8.8) 0(73.722,11.34) 0(73.722,13.88) 0(73.722,16.42) 0(73.722,18.96) 0(73.722,21.5) 0(73.722,24.04) 0(73.722,26.58) 0(73.722,29.12) 0(73.722,31.66) 0(73.722,34.2) 0(73.722,36.74) 0(73.722,39.28) 0(73.722,41.82) 0(73.722,44.36) 0(73.722,54.52) 0(73.722,57.06) 0(73.722,115.48) 0(73.722,118.02) 0(76.262,8.8) 0(76.262,11.34) 0(76.262,13.88) 0(76.262,16.42) 0(76.262,18.96) 0(76.262,21.5) 0(76.262,24.04) 0(76.262,26.58) 0(76.262,29.12) 0(76.262,31.66) 0(76.262,34.2) 0(76.262,36.74) 0(76.262,39.28) 0(76.262,41.82) 0(76.262,44.36) 0(76.262,54.52) 0(76.262,57.06) 0(76.262,115.48) 0(76.262,118.02) 0(78.802,8.8) 0(78.802,11.34) 0(78.802,13.88) 0(78.802,16.42) 0(78.802,18.96) 0(78.802,21.5) 0(78.802,24.04) 0(78.802,26.58) 0(78.802,29.12) 0(78.802,31.66) 0(78.802,34.2) 0(78.802,36.74) 0(78.802,39.28) 0(78.802,41.82) 0(78.802,44.36) 0(78.802,54.52) 0(78.802,57.06) 0(78.802,115.48) 0(78.802,118.02) 0(81.342,8.8) 0(81.342,11.34) 0(81.342,13.88) 0(81.342,16.42) 0(81.342,18.96) 0(81.342,21.5) 0(81.342,24.04) 0(81.342,26.58) 0(81.342,29.12) 0(81.342,31.66) 0(81.342,34.2) 0(81.342,36.74) 0(81.342,39.28) 0(81.342,41.82) 0(81.342,44.36) 0(81.342,54.52) 0(81.342,57.06) 0(81.342,118.02) 0(83.882,8.8) 0(83.882,11.34) 0(83.882,13.88) 0(83.882,16.42) 0(83.882,18.96) 0(83.882,21.5) 0(83.882,24.04) 0(83.882,26.58) 0(83.882,29.12) 0(83.882,31.66) 0(83.882,34.2) 0(83.882,36.74) 0(83.882,39.28) 0(83.882,41.82) 0(83.882,44.36) 0(83.882,54.52) 0(83.882,57.06) 0(83.882,118.02) 0(83.942,128.12) 0(86.422,8.8) 0(86.422,11.34) 0(86.422,13.88) 0(86.422,16.42) 0(86.422,18.96) 0(86.422,21.5) 0(86.422,24.04) 0(86.422,26.58) 0(86.422,29.12) 0(86.422,31.66) 0(86.422,34.2) 0(86.422,36.74) 0(86.422,39.28) 0(86.422,41.82) 0(86.422,44.36) 0(86.422,54.52) 0(86.422,57.06) 0(86.422,115.48) 0(86.422,118.02) 0(86.482,128.12) 0(88.962,8.8) 0(88.962,11.34) 0(88.962,13.88) 0(88.962,16.42) 0(88.962,18.96) 0(88.962,21.5) 0(88.962,24.04) 0(88.962,26.58) 0(88.962,29.12) 0(88.962,31.66) 0(88.962,34.2) 0(88.962,36.74) 0(88.962,39.28) 0(88.962,41.82) 0(88.962,44.36) 0(88.962,54.52) 0(88.962,57.06) 0(88.962,115.48) 0(88.962,118.02) 0(91.502,8.8) 0(91.502,11.34) 0(91.502,13.88) 0(91.502,16.42) 0(91.502,18.96) 0(91.502,21.5) 0(91.502,24.04) 0(91.502,26.58) 0(91.502,29.12) 0(91.502,31.66) 0(91.502,34.2) 0(91.502,36.74) 0(91.502,39.28) 0(91.502,41.82) 0(91.502,44.36) 0(91.502,54.52) 0(91.502,57.06) 0(91.502,115.48) 0(91.502,118.02) 0(94.042,8.8) 0(94.042,11.34) 0(94.042,13.88) 0(94.042,16.42) 0(94.042,18.96) 0(94.042,21.5) 0(94.042,24.04) 0(94.042,26.58) 0(94.042,29.12) 0(94.042,31.66) 0(94.042,34.2) 0(94.042,36.74) 0(94.042,39.28) 0(94.042,41.82) 0(94.042,44.36) 0(94.042,54.52) 0(94.042,57.06) 0(94.042,115.48) 0(94.042,118.02) 0(94.102,128.12) 0(96.582,8.8) 0(96.582,11.34) 0(96.582,13.88) 0(96.582,16.42) 0(96.582,18.96) 0(96.582,21.5) 0(96.582,24.04) 0(96.582,26.58) 0(96.582,29.12) 0(96.582,31.66) 0(96.582,34.2) 0(96.582,36.74) 0(96.582,39.28) 0(96.582,41.82) 0(96.582,44.36) 0(96.582,54.52) 0(96.582,57.06) 0(96.582,115.48) 0(96.582,118.02) 0(96.642,128.12) 0(99.122,8.8) 0(99.122,11.34) 0(99.122,13.88) 0(99.122,16.42) 0(99.122,18.96) 0(99.122,21.5) 0(99.122,24.04) 0(99.122,26.58) 0(99.122,29.12) 0(99.122,31.66) 0(99.122,34.2) 0(99.122,36.74) 0(99.122,39.28) 0(99.122,41.82) 0(99.122,44.36) 0(99.122,54.52) 0(99.122,57.06) 0(99.122,115.48) 0(99.122,118.02) 0(101.662,8.8) 0(101.662,11.34) 0(101.662,13.88) 0(101.662,16.42) 0(101.662,18.96) 0(101.662,21.5) 0(101.662,24.04) 0(101.662,26.58) 0(101.662,29.12) 0(101.662,31.66) 0(101.662,34.2) 0(101.662,36.74) 0(101.662,39.28) 0(101.662,41.82) 0(101.662,44.36) 0(101.662,54.52) 0(101.662,57.06) 0(101.662,115.48) 0(101.662,118.02) 0(104.202,8.8) 0(104.202,11.34) 0(104.202,13.88) 0(104.202,16.42) 0(104.202,18.96) 0(104.202,21.5) 0(104.202,24.04) 0(104.202,26.58) 0(104.202,29.12) 0(104.202,31.66) 0(104.202,34.2) 0(104.202,36.74) 0(104.202,39.28) 0(104.202,41.82) 0(104.202,44.36) 0(104.202,54.52) 0(104.202,57.06) 0(104.202,115.48) 0(104.202,118.02) 0(106.742,8.8) 0(106.742,11.34) 0(106.742,13.88) 0(106.742,16.42) 0(106.742,18.96) 0(106.742,21.5) 0(106.742,24.04) 0(106.742,26.58) 0(106.742,29.12) 0(106.742,31.66) 0(106.742,34.2) 0(106.742,36.74) 0(106.742,39.28) 0(106.742,41.82) 0(106.742,44.36) 0(106.742,54.52) 0(106.742,57.06) 0(106.742,115.48) 0(106.742,118.02) 0(109.282,8.8) 0(109.282,11.34) 0(109.282,13.88) 0(109.282,16.42) 0(109.282,18.96) 0(109.282,21.5) 0(109.282,24.04) 0(109.282,26.58) 0(109.282,29.12) 0(109.282,31.66) 0(109.282,34.2) 0(109.282,36.74) 0(109.282,39.28) 0(109.282,41.82) 0(109.282,44.36) 0(109.282,54.52) 0(109.282,57.06) 0(109.282,59.6) 0(109.282,62.14) 0(109.282,64.68) 0(109.282,67.22) 0(109.282,69.76) 0(109.282,72.3) 0(109.282,74.84) 0(109.282,77.38) 0(109.282,79.92) 0(109.282,82.46) 0(109.282,85) 0(109.282,87.54) 0(109.282,90.08) 0(109.282,92.62) 0(109.282,95.16) 0(109.282,115.48) 0(109.282,118.02) 0(111.822,8.8) 0(111.822,11.34) 0(111.822,13.88) 0(111.822,16.42) 0(111.822,18.96) 0(111.822,21.5) 0(111.822,24.04) 0(111.822,26.58) 0(111.822,29.12) 0(111.822,31.66) 0(111.822,34.2) 0(111.822,36.74) 0(111.822,39.28) 0(111.822,41.82) 0(111.822,44.36) 0(111.822,57.06) 0(111.822,59.6) 0(111.822,62.14) 0(111.822,64.68) 0(111.822,67.22) 0(111.822,69.76) 0(111.822,72.3) 0(111.822,74.84) 0(111.822,77.38) 0(111.822,79.92) 0(111.822,82.46) 0(111.822,85) 0(111.822,87.54) 0(111.822,90.08) 0(111.822,92.62) 0(111.822,95.16) 0(111.822,97.7) 0(111.822,100.24) 0(111.822,102.78) 0(111.822,105.32) 0(111.822,107.86) 0(111.822,110.4) 0(111.822,112.94) 0(111.822,115.48) 0(114.362,8.8) 0(114.362,11.34) 0(114.362,13.88) 0(114.362,16.42) 0(114.362,18.96) 0(114.362,21.5) 0(114.362,24.04) 0(114.362,26.58) 0(114.362,29.12) 0(114.362,31.66) 0(114.362,34.2) 0(114.362,36.74) 0(114.362,39.28) 0(114.362,41.82) 0(114.362,44.36) 0(116.902,8.8) 0(116.902,11.34) 0(116.902,13.88) 0(116.902,16.42) 0(116.902,18.96) 0(116.902,21.5) 0(116.902,24.04) 0(116.902,26.58) 0(116.902,29.12) 0(116.902,31.66) 0(116.902,34.2) 0(116.902,36.74) 0(116.902,39.28) 0(116.902,41.82) 0(116.902,44.36) 0(119.442,8.8) 0(119.442,11.34) 0(119.442,13.88) 0(119.442,16.42) 0(119.442,18.96) 0(119.442,21.5) 0(119.442,24.04) 0(119.442,26.58) 0(119.442,29.12) 0(119.442,31.66) 0(119.442,34.2) 0(119.442,36.74) 0(119.442,39.28) 0(119.442,41.82) 0(119.442,44.36) 0(121.982,8.8) 0(121.982,11.34) 0(121.982,13.88) 0(121.982,16.42) 0(121.982,18.96) 0(121.982,21.5) 0(121.982,24.04) 0(121.982,26.58) 0(121.982,29.12) 0(121.982,31.66) 0(121.982,34.2) 0(121.982,36.74) 0(121.982,39.28) 0(121.982,41.82) 0(121.982,44.36) 0(121.982,46.9) 0(121.982,49.44) 0(121.982,51.98) 0(121.982,54.52) 0(121.982,57.06) 0(121.982,59.6) 0(121.982,62.14) 0(121.982,64.68) 0(121.982,67.22) 0(121.982,69.76) 0(121.982,72.3) 0(121.982,74.84) 0(121.982,77.38) 0(121.982,79.92) 0(121.982,82.46) 0(121.982,85) 0(121.982,87.54) 0(121.982,90.08) 0(121.982,92.62) 0(121.982,95.16) 0(121.982,97.7) 0(121.982,100.24) 0(121.982,102.78) 0(121.982,105.32) 0(121.982,107.86) 0(121.982,110.4) 0(121.982,112.94) 0(121.982,115.48) 0(121.982,120.56) 0(121.982,123.1) 0(124.522,8.8) 0(124.522,11.34) 0(124.522,13.88) 0(124.522,16.42) 0(124.522,18.96) 0(124.522,21.5) 0(124.522,24.04) 0(124.522,26.58) 0(124.522,29.12) 0(124.522,31.66) 0(124.522,34.2) 0(124.522,36.74) 0(124.522,39.28) 0(124.522,41.82) 0(124.522,44.36) 0(124.522,46.9) 0(124.522,49.44) 0(124.522,51.98) 0(124.522,54.52) 0(124.522,57.06) 0(124.522,59.6) 0(124.522,62.14) 0(124.522,64.68) 0(124.522,67.22) 0(124.522,69.76) 0(124.522,72.3) 0(124.522,74.84) 0(124.522,77.38) 0(124.522,79.92) 0(124.522,82.46) 0(124.522,85) 0(124.522,87.54) 0(124.522,90.08) 0(124.522,92.62) 0(124.522,95.16) 0(124.522,97.7) 0(124.522,100.24) 0(124.522,102.78) 0(124.522,105.32) 0(124.522,107.86) 0(124.522,110.4) 0(124.522,112.94) 0(124.522,115.48) 0(127.062,8.8) 0(127.062,11.34) 0(127.062,13.88) 0(127.062,16.42) 0(127.062,18.96) 0(127.062,21.5) 0(127.062,24.04) 0(127.062,26.58) 0(127.062,29.12) 0(127.062,31.66) 0(127.062,34.2) 0(127.062,36.74) 0(127.062,39.28) 0(127.062,41.82) 0(127.062,44.36) 0(127.062,46.9) 0(127.062,49.44) 0(127.062,51.98) 0(127.062,54.52) 0(127.062,57.06) 0(127.062,59.6) 0(127.062,62.14) 0(127.062,64.68) 0(127.062,67.22) 0(127.062,69.76) 0(127.062,72.3) 0(127.062,74.84) 0(127.062,77.38) 0(127.062,79.92) 0(127.062,82.46) 0(127.062,85) 0(127.062,87.54) 0(127.062,90.08) 0(127.062,92.62) 0(127.062,95.16) 0(127.062,97.7) 0(127.062,100.24) 0(127.062,102.78) 0(127.062,105.32) 0(127.062,107.86) 0(127.062,110.4) 0(127.062,112.94) 0(127.062,115.48) 0(127.062,120.56) 0(127.062,123.1) 0(129.602,8.8) 0(129.602,11.34) 0(129.602,13.88) 0(129.602,16.42) 0(129.602,18.96) 0(129.602,21.5) 0(129.602,24.04) 0(129.602,26.58) 0(129.602,29.12) 0(129.602,31.66) 0(129.602,34.2) 0(129.602,36.74) 0(129.602,39.28) 0(129.602,41.82) 0(129.602,44.36) 0(129.602,46.9) 0(129.602,49.44) 0(129.602,51.98) 0(129.602,54.52) 0(129.602,57.06) 0(129.602,59.6) 0(129.602,62.14) 0(129.602,64.68) 0(129.602,67.22) 0(129.602,69.76) 0(129.602,72.3) 0(129.602,74.84) 0(129.602,77.38) 0(129.602,79.92) 0(129.602,82.46) 0(129.602,85) 0(129.602,87.54) 0(129.602,90.08) 0(129.602,92.62) 0(129.602,95.16) 0(129.602,97.7) 0(129.602,100.24) 0(129.602,102.78) 0(129.602,105.32) 0(129.602,107.86) 0(129.602,110.4) 0(129.602,112.94) 0(129.602,115.48) 0(129.602,120.56) 0(129.602,123.1) 0(132.142,8.8) 0(132.142,11.34) 0(132.142,13.88) 0(132.142,16.42) 0(132.142,18.96) 0(132.142,21.5) 0(132.142,24.04) 0(132.142,26.58) 0(132.142,29.12) 0(132.142,31.66) 0(132.142,34.2) 0(132.142,36.74) 0(132.142,39.28) 0(132.142,41.82) 0(132.142,44.36) 0(132.142,46.9) 0(132.142,49.44) 0(132.142,51.98) 0(132.142,54.52) 0(132.142,57.06) 0(132.142,59.6) 0(132.142,62.14) 0(132.142,64.68) 0(132.142,67.22) 0(132.142,69.76) 0(132.142,72.3) 0(132.142,74.84) 0(132.142,77.38) 0(132.142,79.92) 0(132.142,82.46) 0(132.142,85) 0(132.142,87.54) 0(132.142,90.08) 0(132.142,92.62) 0(132.142,95.16) 0(132.142,97.7) 0(132.142,100.24) 0(132.142,102.78) 0(132.142,105.32) 0(132.142,107.86) 0(132.142,110.4) 0(132.142,112.94) 0(132.142,115.48) 0(132.142,120.56) 0(132.142,123.1) 0(134.682,8.8) 0(134.682,11.34) 0(134.682,13.88) 0(134.682,16.42) 0(134.682,18.96) 0(134.682,21.5) 0(134.682,24.04) 0(134.682,26.58) 0(134.682,29.12) 0(134.682,31.66) 0(134.682,34.2) 0(134.682,36.74) 0(134.682,39.28) 0(134.682,41.82) 0(134.682,44.36) 0(134.682,46.9) 0(134.682,49.44) 0(134.682,51.98) 0(134.682,54.52) 0(134.682,57.06) 0(134.682,59.6) 0(134.682,62.14) 0(134.682,64.68) 0(134.682,67.22) 0(134.682,69.76) 0(134.682,72.3) 0(134.682,74.84) 0(134.682,77.38) 0(134.682,79.92) 0(134.682,82.46) 0(134.682,85) 0(134.682,87.54) 0(134.682,90.08) 0(134.682,92.62) 0(134.682,95.16) 0(134.682,97.7) 0(134.682,100.24) 0(134.682,102.78) 0(134.682,105.32) 0(134.682,107.86) 0(134.682,110.4) 0(134.682,112.94) 0(134.682,115.48) 0(134.682,120.56) 0(134.682,123.1) 0(137.222,8.8) 0(137.222,11.34) 0(137.222,13.88) 0(137.222,16.42) 0(137.222,18.96) 0(137.222,21.5) 0(137.222,24.04) 0(137.222,26.58) 0(137.222,29.12) 0(137.222,31.66) 0(137.222,34.2) 0(137.222,36.74) 0(137.222,39.28) 0(137.222,41.82) 0(137.222,44.36) 0(137.222,46.9) 0(137.222,49.44) 0(137.222,51.98) 0(137.222,54.52) 0(137.222,57.06) 0(137.222,59.6) 0(137.222,62.14) 0(137.222,64.68) 0(137.222,67.22) 0(137.222,69.76) 0(137.222,72.3) 0(137.222,74.84) 0(137.222,77.38) 0(137.222,79.92) 0(137.222,82.46) 0(137.222,85) 0(137.222,87.54) 0(137.222,90.08) 0(137.222,92.62) 0(137.222,95.16) 0(137.222,97.7) 0(137.222,100.24) 0(137.222,102.78) 0(137.222,105.32) 0(137.222,107.86) 0(137.222,110.4) 0(137.222,112.94) 0(137.222,115.48) 0(139.762,8.8) 0(139.762,11.34) 0(139.762,13.88) 0(139.762,16.42) 0(139.762,18.96) 0(139.762,21.5) 0(139.762,24.04) 0(139.762,26.58) 0(139.762,29.12) 0(139.762,31.66) 0(139.762,34.2) 0(139.762,36.74) 0(139.762,39.28) 0(139.762,41.82) 0(139.762,44.36) 0(139.762,46.9) 0(139.762,49.44) 0(139.762,51.98) 0(139.762,54.52) 0(139.762,57.06) 0(139.762,59.6) 0(139.762,62.14) 0(139.762,64.68) 0(139.762,67.22) 0(139.762,69.76) 0(139.762,72.3) 0(139.762,74.84) 0(139.762,77.38) 0(139.762,79.92) 0(139.762,82.46) 0(139.762,85) 0(139.762,87.54) 0(139.762,90.08) 0(139.762,92.62) 0(139.762,95.16) 0(139.762,97.7) 0(139.762,100.24) 0(139.762,102.78) 0(139.762,105.32) 0(139.762,107.86) 0(139.762,110.4) 0(139.762,112.94) 0(139.762,115.48) 0(139.762,118.02) 0(139.762,120.56) 0(139.762,123.1) 0(142.302,8.8) 0(142.302,11.34) 0(142.302,13.88) 0(142.302,16.42) 0(142.302,18.96) 0(142.302,21.5) 0(142.302,24.04) 0(142.302,26.58) 0(142.302,29.12) 0(142.302,31.66) 0(142.302,34.2) 0(142.302,36.74) 0(142.302,39.28) 0(142.302,41.82) 0(142.302,44.36) 0(142.302,46.9) 0(142.302,49.44) 0(142.302,51.98) 0(142.302,54.52) 0(142.302,57.06) 0(142.302,59.6) 0(142.302,62.14) 0(142.302,64.68) 0(142.302,67.22) 0(142.302,69.76) 0(142.302,72.3) 0(142.302,74.84) 0(142.302,77.38) 0(142.302,79.92) 0(142.302,82.46) 0(142.302,85) 0(142.302,87.54) 0(142.302,90.08) 0(142.302,92.62) 0(142.302,95.16) 0(142.302,97.7) 0(142.302,100.24) 0(142.302,102.78) 0(142.302,105.32) 0(142.302,107.86) 0(142.302,110.4) 0(142.302,112.94) 0(142.302,115.48) 0(142.302,118.02) 0(142.302,120.56) 0(142.302,123.1) 0(144.842,8.8) 0(144.842,11.34) 0(144.842,13.88) 0(144.842,16.42) 0(144.842,18.96) 0(144.842,21.5) 0(144.842,24.04) 0(144.842,26.58) 0(144.842,29.12) 0(144.842,31.66) 0(144.842,34.2) 0(144.842,36.74) 0(144.842,39.28) 0(144.842,41.82) 0(144.842,44.36) 0(144.842,46.9) 0(144.842,49.44) 0(144.842,51.98) 0(144.842,54.52) 0(144.842,57.06) 0(144.842,59.6) 0(144.842,62.14) 0(144.842,64.68) 0(144.842,67.22) 0(144.842,69.76) 0(144.842,72.3) 0(144.842,74.84) 0(144.842,77.38) 0(144.842,79.92) 0(144.842,82.46) 0(144.842,85) 0(144.842,87.54) 0(144.842,90.08) 0(144.842,92.62) 0(144.842,95.16) 0(144.842,97.7) 0(144.842,100.24) 0(144.842,102.78) 0(144.842,105.32) 0(144.842,107.86) 0(144.842,110.4) 0(144.842,112.94) 0(144.842,115.48) 0(147.382,8.8) 0(147.382,11.34) 0(147.382,13.88) 0(147.382,16.42) 0(147.382,18.96) 0(147.382,21.5) 0(147.382,24.04) 0(147.382,26.58) 0(147.382,29.12) 0(147.382,31.66) 0(147.382,34.2) 0(147.382,36.74) 0(147.382,39.28) 0(147.382,41.82) 0(147.382,44.36) 0(147.382,46.9) 0(147.382,49.44) 0(147.382,51.98) 0(147.382,54.52) 0(147.382,57.06) 0(147.382,59.6) 0(147.382,62.14) 0(147.382,64.68) 0(147.382,67.22) 0(147.382,69.76) 0(147.382,72.3) 0(147.382,74.84) 0(147.382,77.38) 0(147.382,79.92) 0(147.382,82.46) 0(147.382,85) 0(147.382,87.54) 0(147.382,90.08) 0(147.382,92.62) 0(147.382,95.16) 0(147.382,97.7) 0(147.382,100.24) 0(147.382,102.78) 0(147.382,105.32) 0(147.382,107.86) 0(147.382,110.4) 0(147.382,112.94) 0(147.382,115.48) 0(147.382,120.56) 0(147.382,123.1) 0(147.581,156.15) 0(149.922,8.8) 0(149.922,11.34) 0(149.922,13.88) 0(149.922,16.42) 0(149.922,18.96) 0(149.922,21.5) 0(149.922,24.04) 0(149.922,26.58) 0(149.922,29.12) 0(149.922,31.66) 0(149.922,34.2) 0(149.922,36.74) 0(149.922,39.28) 0(149.922,41.82) 0(149.922,44.36) 0(149.922,46.9) 0(149.922,49.44) 0(149.922,51.98) 0(149.922,54.52) 0(149.922,57.06) 0(149.922,59.6) 0(149.922,62.14) 0(149.922,64.68) 0(149.922,67.22) 0(149.922,69.76) 0(149.922,72.3) 0(149.922,74.84) 0(149.922,77.38) 0(149.922,79.92) 0(149.922,82.46) 0(149.922,85) 0(149.922,87.54) 0(149.922,90.08) 0(149.922,92.62) 0(149.922,95.16) 0(149.922,97.7) 0(149.922,100.24) 0(149.922,102.78) 0(149.922,105.32) 0(149.922,107.86) 0(149.922,110.4) 0(149.922,112.94) 0(149.922,115.48) 0(149.922,120.56) 0(149.922,123.1) 0(150.042,156.15) 0(152.462,8.8) 0(152.462,11.34) 0(152.462,13.88) 0(152.462,16.42) 0(152.462,18.96) 0(152.462,21.5) 0(152.462,24.04) 0(152.462,26.58) 0(152.462,29.12) 0(152.462,31.66) 0(152.462,34.2) 0(152.462,36.74) 0(152.462,39.28) 0(152.462,41.82) 0(152.462,44.36) 0(152.462,46.9) 0(152.462,49.44) 0(152.462,51.98) 0(152.462,54.52) 0(152.462,57.06) 0(152.462,59.6) 0(152.462,62.14) 0(152.462,64.68) 0(152.462,67.22) 0(152.462,69.76) 0(152.462,72.3) 0(152.462,74.84) 0(152.462,77.38) 0(152.462,79.92) 0(152.462,82.46) 0(152.462,85) 0(152.462,87.54) 0(152.462,90.08) 0(152.462,92.62) 0(152.462,95.16) 0(152.462,97.7) 0(152.462,100.24) 0(152.462,102.78) 0(152.462,105.32) 0(152.462,107.86) 0(152.462,110.4) 0(152.462,112.94) 0(152.462,115.48) 0(152.462,120.56) 0(152.462,123.1) 0(155.002,8.8) 0(155.002,11.34) 0(155.002,13.88) 0(155.002,16.42) 0(155.002,18.96) 0(155.002,21.5) 0(155.002,24.04) 0(155.002,26.58) 0(155.002,29.12) 0(155.002,31.66) 0(155.002,34.2) 0(155.002,36.74) 0(155.002,39.28) 0(155.002,41.82) 0(155.002,44.36) 0(155.002,46.9) 0(155.002,49.44) 0(155.002,51.98) 0(155.002,54.52) 0(155.002,57.06) 0(155.002,59.6) 0(155.002,62.14) 0(155.002,64.68) 0(155.002,67.22) 0(155.002,69.76) 0(155.002,72.3) 0(155.002,74.84) 0(155.002,77.38) 0(155.002,79.92) 0(155.002,82.46) 0(155.002,85) 0(155.002,87.54) 0(155.002,90.08) 0(155.002,92.62) 0(155.002,95.16) 0(155.002,97.7) 0(155.002,100.24) 0(155.002,102.78) 0(155.002,105.32) 0(155.002,107.86) 0(155.002,110.4) 0(155.002,112.94) 0(155.002,115.48) 0(155.002,120.56) 0(155.002,123.1)
  oval 1.1x1 hole 0.4 mask+0.05: 0(59.06,72.182) 0(59.06,74.722) 0(59.06,75.992) 0(59.06,77.262) 0(59.06,78.532) 0(59.06,79.802) 0(59.06,81.072) 0(59.06,82.342) 0(59.06,83.612) 0(59.06,84.882) 0(59.06,86.152) 0(59.06,87.422) 0(59.06,88.695) 0(59.06,89.962) 0(59.06,91.232) 0(59.06,92.502) 0(59.06,93.772) 0(59.06,95.042) 0(59.06,96.312) 0(59.06,97.582) 0(59.06,98.852) 0(59.073,73.44) 0(59.085,100.122) 0(59.11,101.385) 0(102.007,73.427) 0(102.032,77.237) 0(102.032,74.697) 0(102.032,75.967) 0(102.032,78.507) 0(102.032,79.777) 0(102.032,81.047) 0(102.032,82.317) 0(102.032,83.587) 0(102.032,84.855) 0(102.032,86.127) 0(102.032,87.397) 0(102.032,88.667) 0(102.032,89.937) 0(102.032,91.207) 0(102.032,92.477) 0(102.032,93.747) 0(102.032,95.017) 0(102.032,96.287) 0(102.032,97.557) 0(102.032,98.827) 0(102.032,100.097)
  oval 1x1.1 hole 0.4 mask+0.05: 0(59.761,102.96) 0(60.454,131.451) 0(62.984,131.451) 0(64.464,107.961) 0(65.464,131.451) 0(65.964,108.261) 0(67.219,65.304) 0(67.234,108.261) 0(68.489,65.279) 0(68.504,108.261) 0(69.759,65.279) 0(69.774,108.261) 0(71.029,65.279) 0(71.044,108.261) 0(72.299,65.279) 0(72.314,108.261) 0(72.964,131.451) 0(73.569,65.279) 0(73.584,108.261) 0(74.839,65.279) 0(74.854,108.261) 0(76.109,65.279) 0(76.124,108.261) 0(77.379,65.279) 0(77.394,108.261) 0(77.884,131.451) 0(78.646,65.279) 0(78.664,108.261) 0(79.604,131.451) 0(79.919,65.279) 0(79.934,108.261) 0(80.904,131.451) 0(81.189,65.279) 0(81.204,108.261) 0(82.174,131.451) 0(82.459,65.279) 0(82.476,108.261) 0(83.729,65.279) 0(83.744,108.261) 0(84.999,65.279) 0(85.014,108.261) 0(86.269,65.279) 0(86.284,108.261) 0(87.539,65.279) 0(87.554,108.261) 0(88.809,65.279) 0(88.824,108.261) 0(90.079,65.279) 0(90.094,108.261) 0(91.349,65.279) 0(91.364,108.261) 0(92.619,65.279) 0(92.634,108.261) 0(93.889,65.279) 0(93.904,108.236) 0(95.159,65.279) 0(101.977,71.74)
  oval 1x1.1 hole 0.4 rot 45 mask+0.05: 0(96.387,66.017) 0(101.287,70.796)
  oval 0.8x1.1 hole 0.4: 0(125.361,129.853) 0(126.644,129.853) 0(127.913,129.853) 0(129.183,129.853) 0(130.454,129.853) 0(131.711,129.853) 0(132.993,129.853) 0(134.263,129.853)
  rrect30% 5.2x5.2 hole 3.2: 1(156.2,156.2) 2(156.2,3.8) 3(3.8,156.2) 4(3.8,3.8)

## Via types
v1: diameter 1.5, hole 0.7, Top to Bottom, tented both sides, 54 vias
v2: diameter 1.1, hole 0.4, Top to Bottom, tented both sides, 49 vias
v3: diameter 1.9, hole 1.05, Top to Bottom, tented both sides, 17 vias
v4: diameter 1.9, hole 1.05, Top to Bottom, 16 vias
v5: diameter 0.9, hole 0.4, Top to Bottom, tented both sides, 2 vias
